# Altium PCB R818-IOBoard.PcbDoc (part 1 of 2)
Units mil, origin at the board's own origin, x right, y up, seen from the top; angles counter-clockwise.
Board outline 4330.71 x 4330.71 mil, 4 copper layers (Top Layer, Layer 2, Layer 1, Bottom Layer), stack 33.574 mil thick; 161 components, 167 nets, 792 pads, 698 vias.
Unrouted connection lines stored in the file: 71.
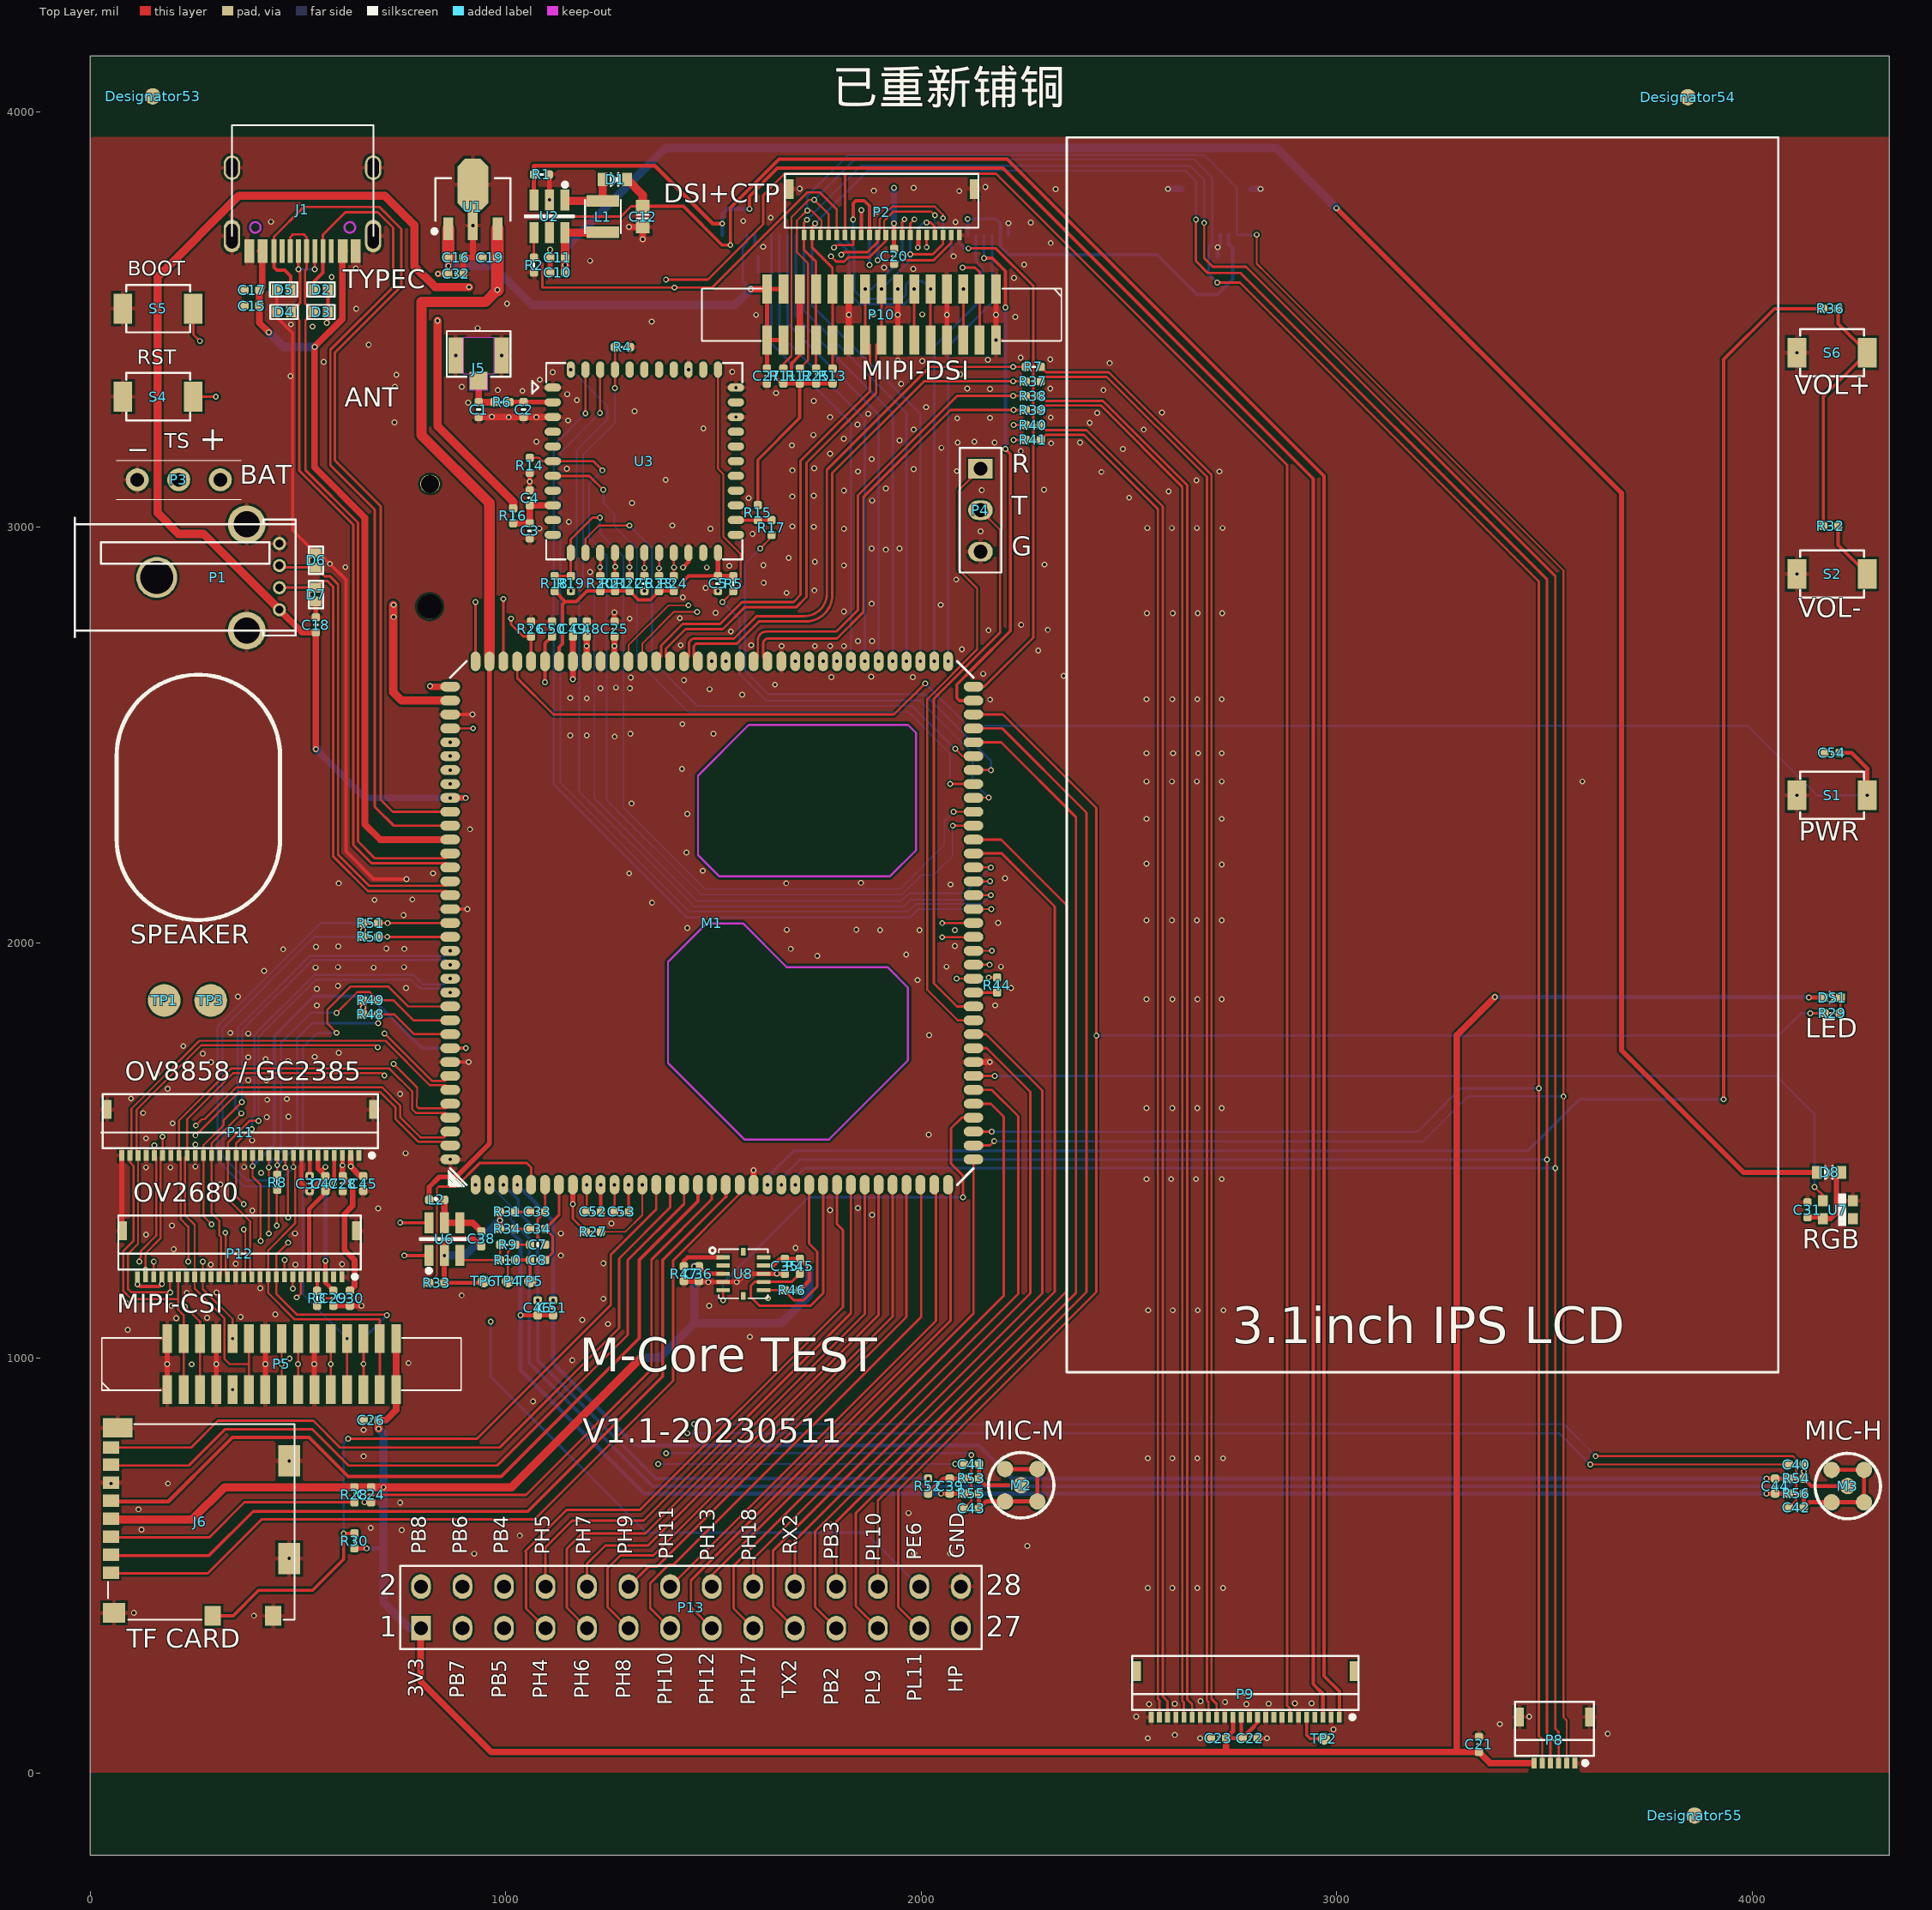
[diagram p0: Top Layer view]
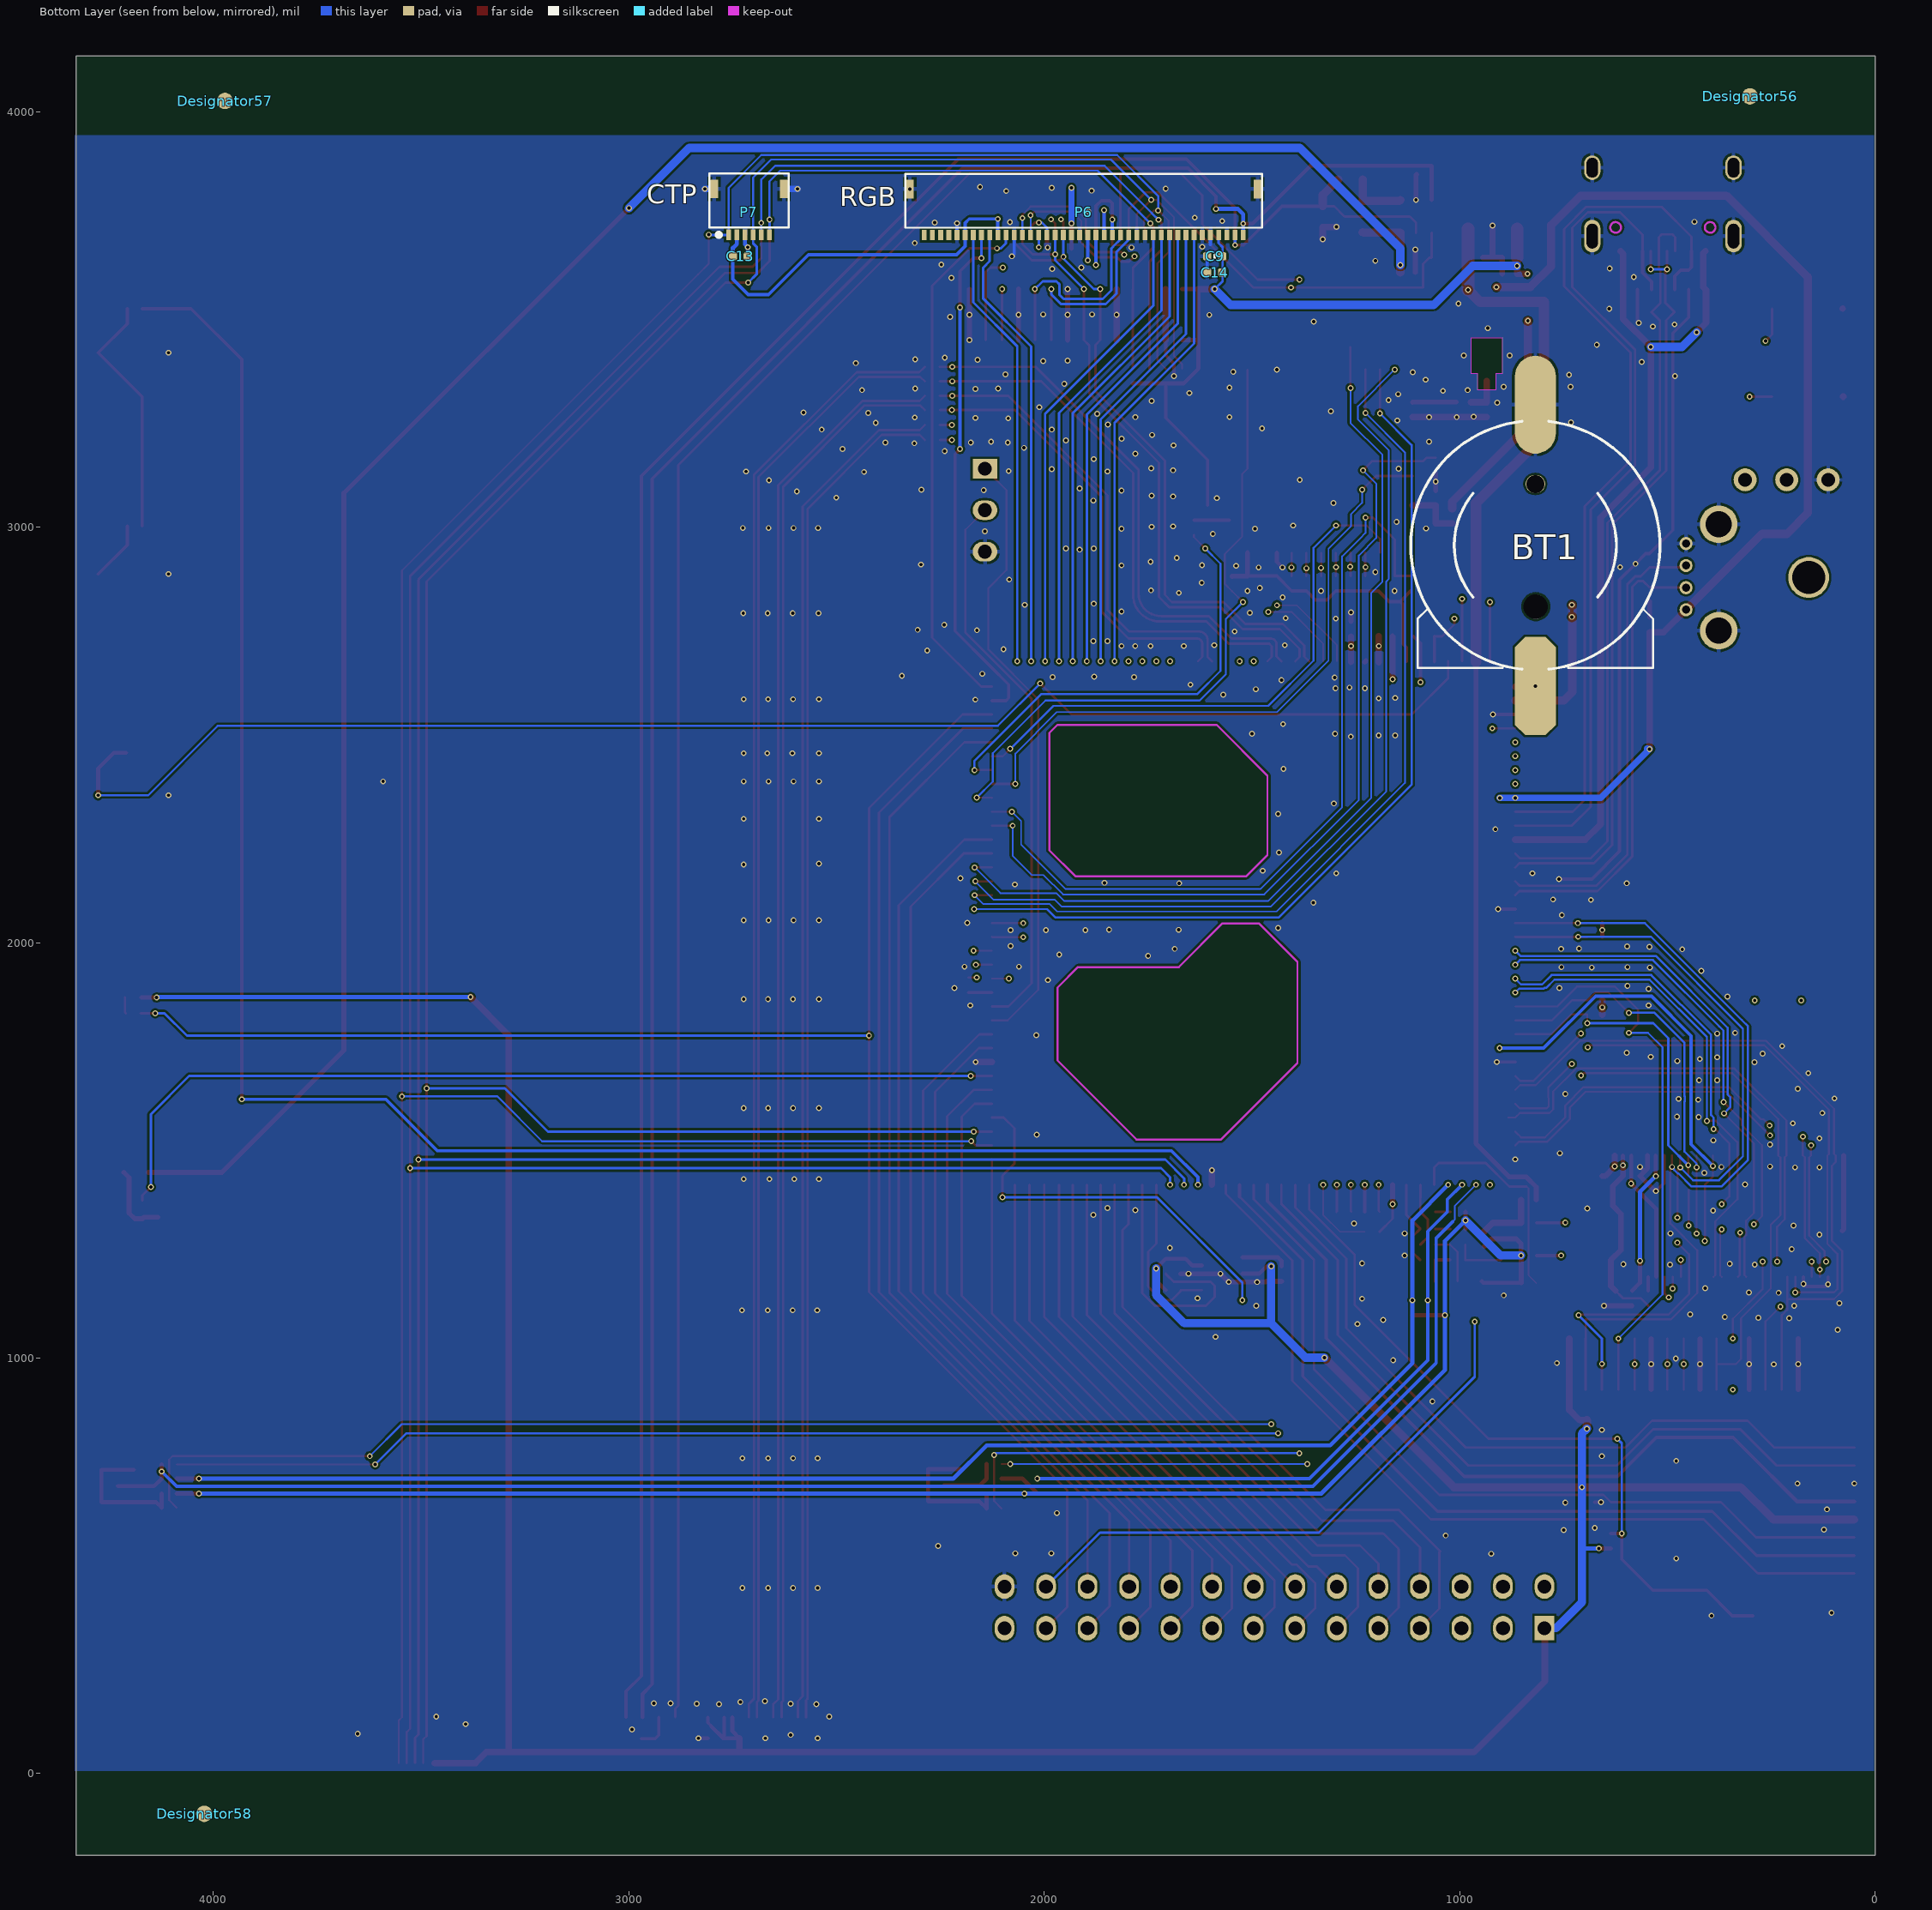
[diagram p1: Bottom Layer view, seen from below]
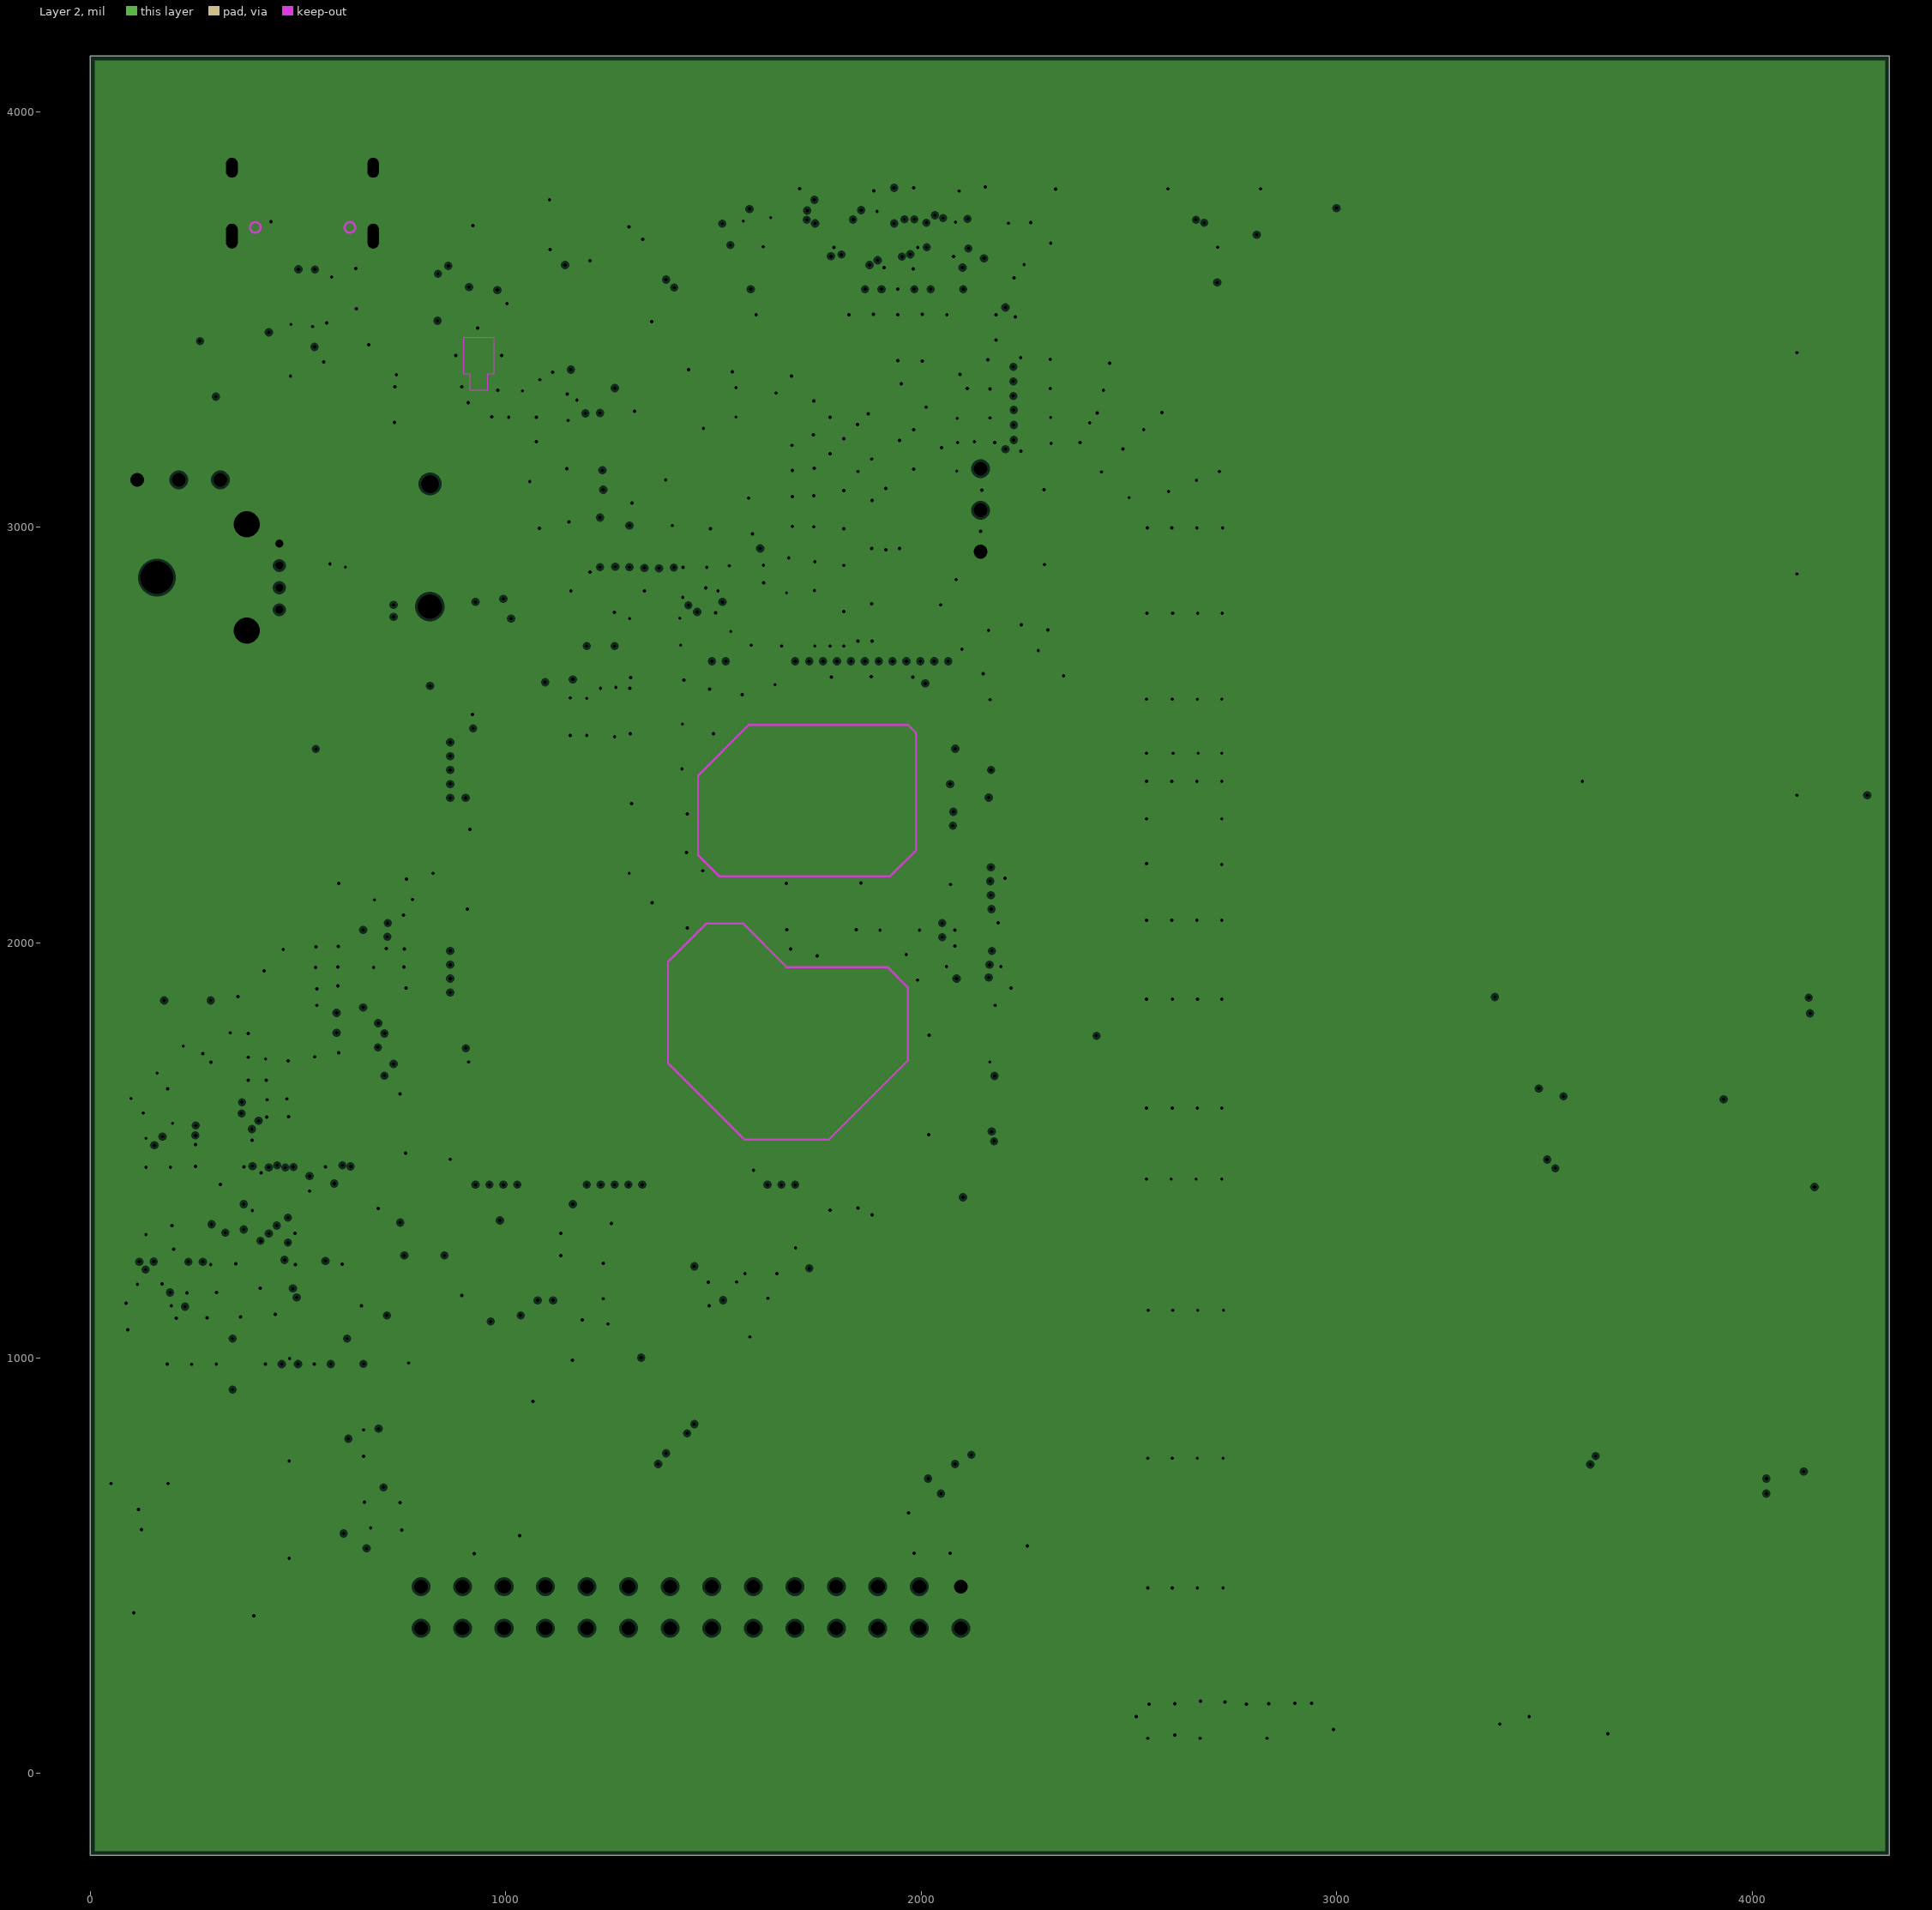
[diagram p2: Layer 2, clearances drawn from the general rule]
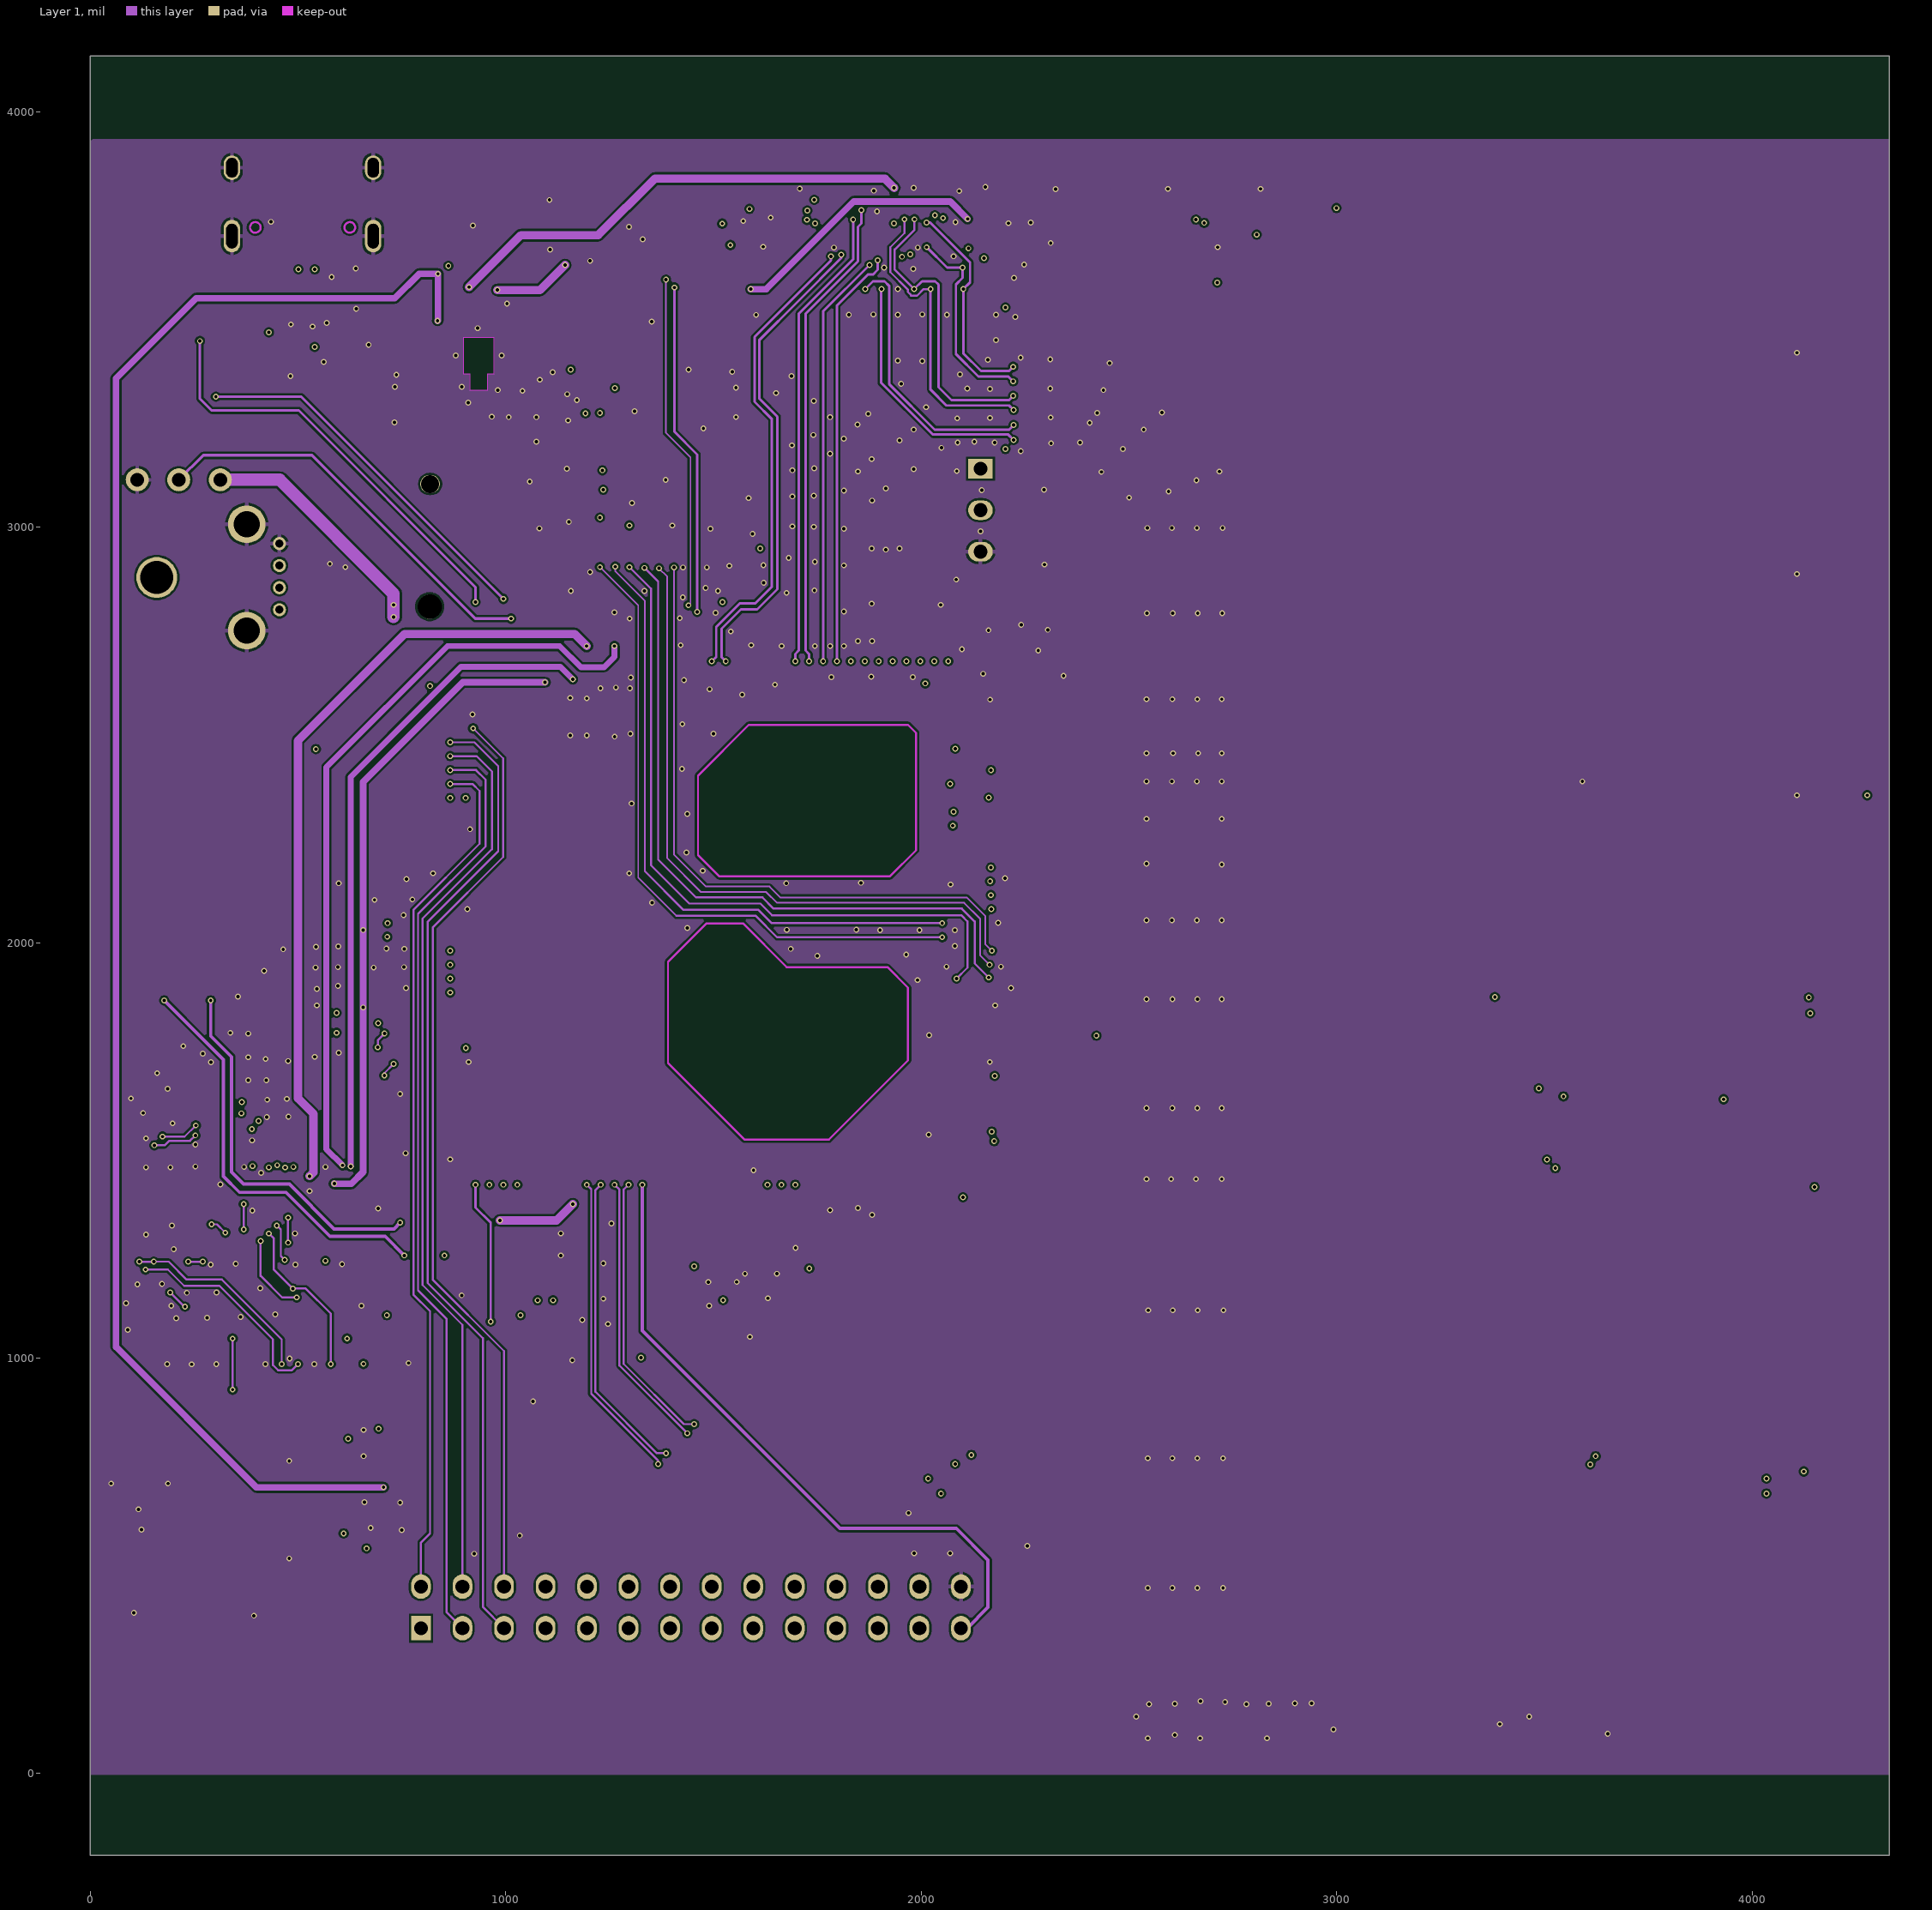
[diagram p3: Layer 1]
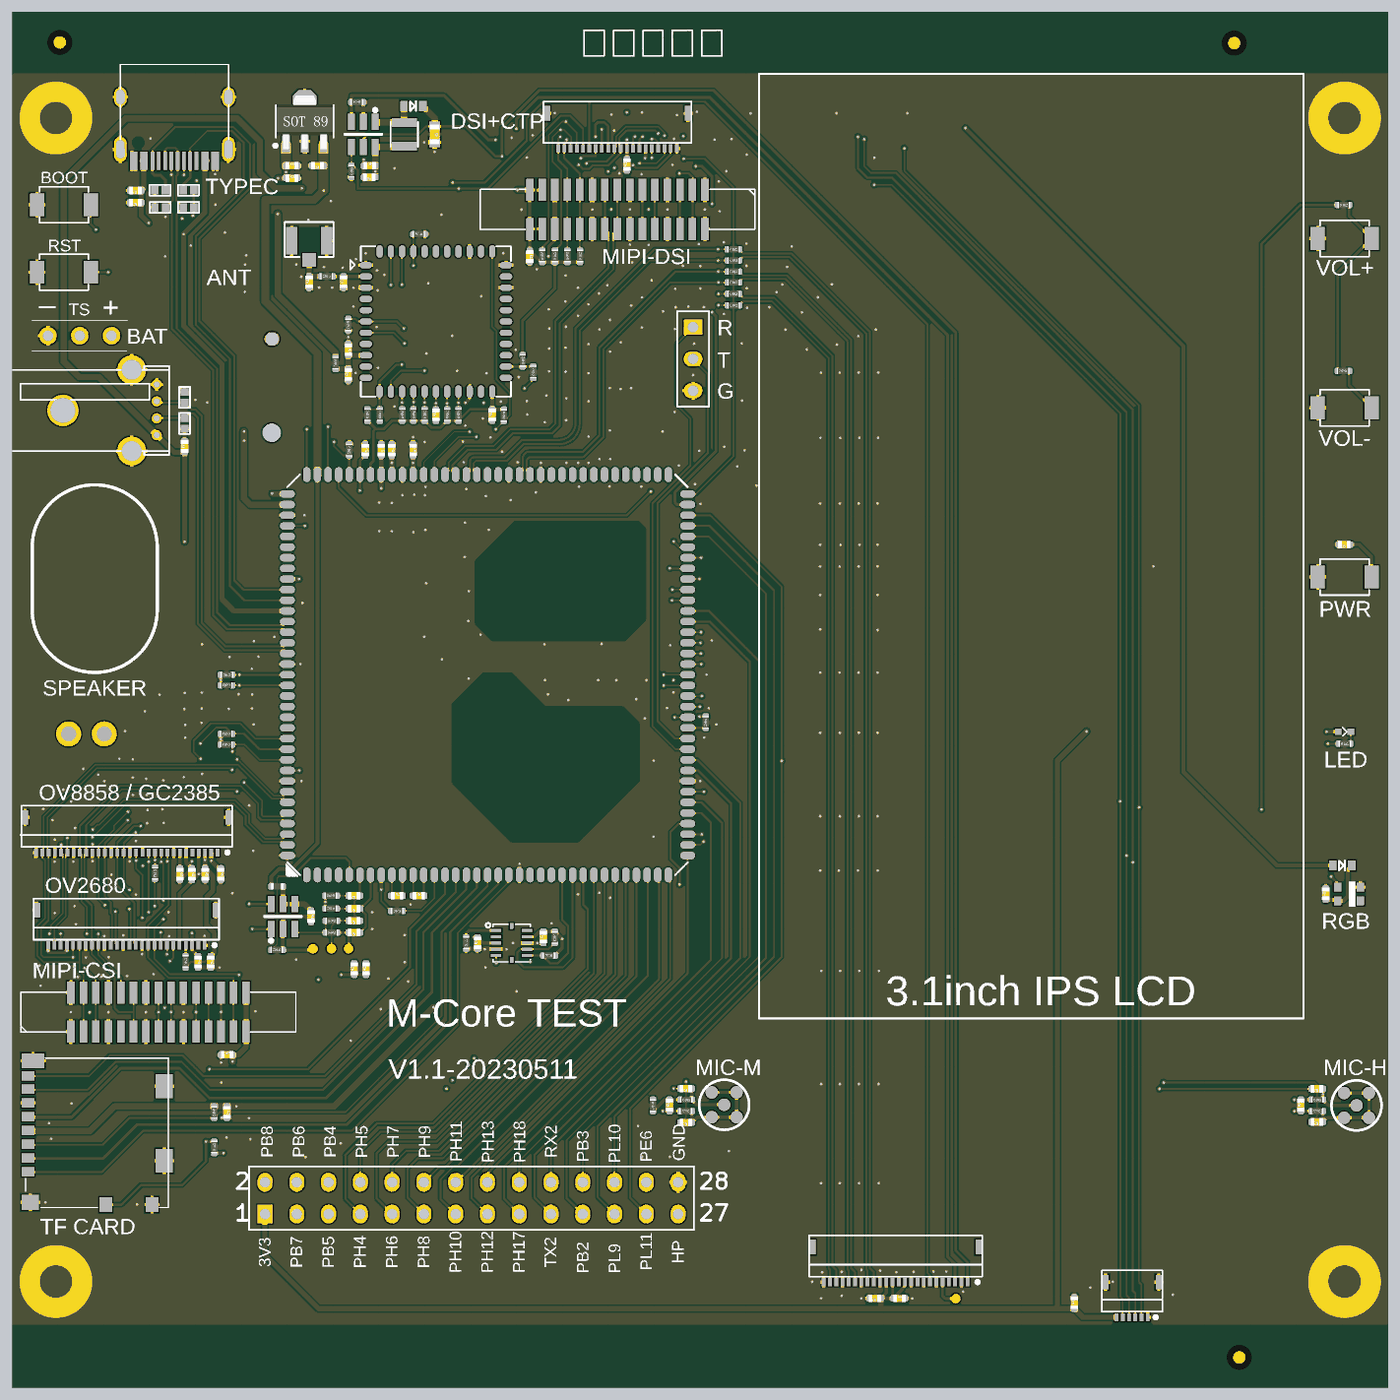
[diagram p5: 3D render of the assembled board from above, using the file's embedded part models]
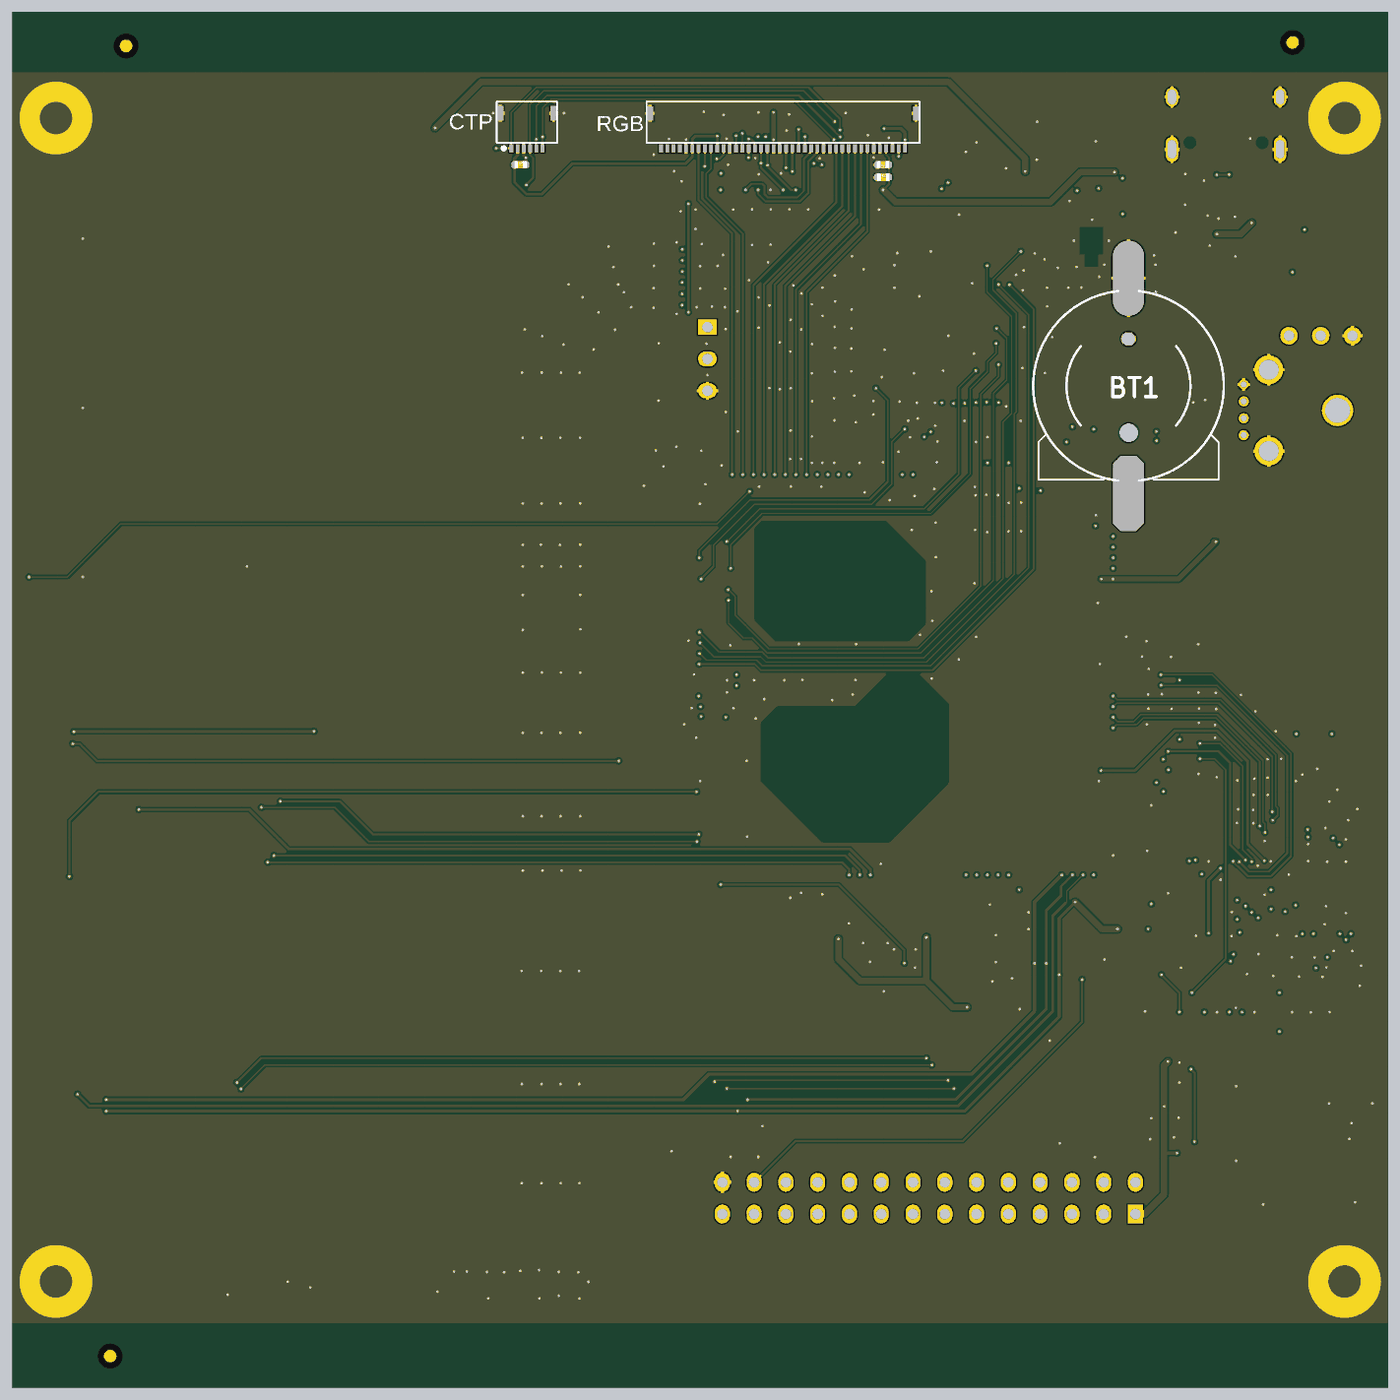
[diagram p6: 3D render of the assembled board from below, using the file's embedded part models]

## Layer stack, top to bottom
Top Solder: solder mask 0.4, Solder Resist, Dk 3.5
Top Layer: signal copper 1.378
Dielectric1: prepreg 18, PR-4, Dk 4.4
Layer 2: plane copper 0.709, net GND
Dielectric 2: prepreg 8.6, PP-023, Dk 4.5
Layer 1: signal copper 0.709
Dielectric 3: prepreg 2.8, PP-006, Dk 4.1
Bottom Layer: signal copper 1.378
Bottom Solder: solder mask 0.4, Solder Resist, Dk 3.5

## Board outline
0,0 0,3937.01 0,4133.86 4330.71,4133.86 4330.71,3937.01 4330.71,0 4330.71,-196.85 0,-196.85

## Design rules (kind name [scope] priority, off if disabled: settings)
AssemblyTestPointUsage [All] p1 off:
AssemblyTestpoint [All] p1 off: testpointundercomponent=TRUE minsize=40 maxsize=100 preferedsize=60 minholesize=0 maxholesize=40 preferedholesize=32 testpointgrid=1 usegrid=TRUE gridtolerance=0.01 allowsidetop=TRUE allowsidebottom=TRUE
Clearance Clearance_1 [All] p1: gap=5 ignorepadtopadclearanceinfootprint=FALSE
Clearance [InPolygon] p2: gap=6 ignorepadtopadclearanceinfootprint=FALSE
ComponentClearance [All] p1 off: gap=1 collisioncheckmode=3 verticalgap=1 showdistances=FALSE
DiffPairsRouting [All] p1: maxlimit=20 minlimit=5.5 mostfreqgap=7 toplayer_minwidth=4 toplayer_maxwidth=8 toplayer_prefwidth=4.6 midlayer1_minwidth=4 midlayer1_maxwidth=8 midlayer1_prefwidth=4.6 bottomlayer_minwidth=4 bottomlayer_maxwidth=8 bottomlayer_prefwidth=4.6 maxuncoupledlength=3000
FabricationTestPointUsage TestPointUsage [All] p1 off: valid=0 allowmultiple=FALSE
FabricationTestpoint Testpoint [(IsPad And (OnTopLayer Or OnBottomLayer))] p1 off: side=3 testpointundercomponent=TRUE minsize=40 maxsize=100 preferedsize=60 minholesize=0 maxholesize=40 preferedholesize=32 testpointgrid=1 allowsidetop=TRUE allowsidebottom=TRUE usegrid=TRUE gridtolerance=0.01
Height [All] p1 off: minheight=0 maxheight=1000 prefheight=500
HoleSize [All] p1: absolutevalues=TRUE maxlimit=150 minlimit=1 maxpercent=80.000 minpercent=20.000
HoleToHoleClearance [All] p1: gap=0 allowstackedmicrovias=TRUE
MinimumSolderMaskSliver [All] p1 off: minsoldermaskwidth=1
NetAntennae [All] p1: netantennaetolerance=10
PlaneClearance [All] p1: clearance=6
PlaneConnect [All] p1: planeconnectstyle=Direct reliefexpansion=20 reliefentries=4 reliefconductorwidth=25 reliefairgap=10
PolygonConnect PolygonConnect_1 [All vs IsPad] p1: connectstyle=Relief reliefconductorwidth=10 reliefentries=4 polygonreliefangle="90 Angle" airgapwidth=6
PolygonConnect PolygonConnect_isvia [All vs IsVia] p2: connectstyle=Direct reliefconductorwidth=10 reliefentries=4 polygonreliefangle="90 Angle" airgapwidth=10
PolygonConnect [All] p3: connectstyle=Direct reliefconductorwidth=8 reliefentries=4 polygonreliefangle="90 Angle" airgapwidth=10
RoutingVias [All] p1: holewidth=8 width=14 viastyle="Through Hole" minholewidth=8 minwidth=14 maxholewidth=100 maxwidth=100
ShortCircuit [InNet('WIFI') vs InNet('GND')] p1 off: allowed=FALSE
SilkToSilkClearance [All] p1: silktosilkclearance=0
SilkToSolderMaskClearance SilkscreenOverComponentPads [IsPad] p1: minsilkscreentomaskgap=0 clearancetoexposedcopper=TRUE
SolderMaskExpansion [All] p1: expansion=4 istentingtop=FALSE
Width [All] p1: maxlimit=100 minlimit=4 preferedwidth=4.72
14 further rules are at their usual default settings.

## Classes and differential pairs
differential pair D3: +D3_P -D3_N
differential pair D2: +D2_P -D2_N
differential pair D1: +D1_P -D1_N
differential pair D0: +D0_P -D0_N
differential pair CK: +CK_P -CK_N
differential pair USB1: +USB1_P -USB1_N
differential pair USB0: +USB0_P -USB0_N

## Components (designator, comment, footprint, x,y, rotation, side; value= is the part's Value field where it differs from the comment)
BT1 "BAT" BAT1220 817.7,2956.43 r180 bottom locked
C1 "NC" C0402 934.7,3283 r90 top
C2 "NC" C0402 1042.7,3283 r90 top
C3 "10uF" C0402 1057.69,2991.37 r90 top
C4 "0.1uF" C0402 1057.69,3070.37 r270 top
C5 "2.2uF" C0402 1510.69,2864.37 r90 top
C6 "NC" C0402 1333.57,2864.37 r90 top
C7 "10uF" C0402 1076.7,1273 r180 top
C8 "10uF" C0402 1076.7,1236 r180 top
C9 "0.1uF" C0402 1589.7,3652 r0 bottom
C10 "10uF" C0402 1124.7,3613 r180 top
C11 "10uF" C0402 1124.7,3649 r0 top
C12 "1uF 50V" C0603 1329.7,3747.7 r270 top
C13 "0.1uF" C0402 2731.7,3652 r180 bottom
C14 "10uF" C0402 1589.7,3613 r180 bottom
C15 "0.1uF" C0402 388.7,3533 r180 top
C16 "10uF" C0402 879.7,3649 r0 top
C17 "10uF" C0402 388.7,3571 r180 top
C18 "10uF" C0402 542.7,2765 r90 top
C19 "10uF" C0402 961.7,3649 r180 top
C20 "0.1uF" C0402 1934.7,3652 r90 top
C21 "0.1uF" C0402 3342.7,70 r90 top
C22 "0.1uF" C0402 2791.7,85 r0 top
C23 "10uF" C0402 2715.7,85 r180 top
C24 "0.1uF" C0402 675.7,671 r270 top
C25 "0.1uF" C0402 1261.7,2755 r270 top
C26 "10uF" C0402 675.7,851 r0 top
C27 "10uF" C0402 1628.7,3364 r270 top
C28 "10uF" C0402 607.58,1420 r270 top
C29 "10uF" C0402 584.7,1144 r270 top
C30 "10uF" C0402 624.7,1144 r270 top
C31 "0.1uF" C0402 4133.7,1357 r90 top
C32 "0.1uF" C0402 879.7,3610 r0 top
C33 "0.1uF" C0402 1076.7,1352 r180 top
C34 "0.1uF" C0402 1076.7,1311 r180 top
C35 "0.1uF" C0402 1671.7,1221 r90 top
C36 "0.1uF" C0402 1464.7,1203 r90 top
C37 "10uF" C0402 527.7,1420 r270 top
C38 "10uF" C0402 940.7,1287 r270 top
C39 "10uF" C0402 2068.7,692 r90 top
C40 "0.1uF" C0402 4106.7,744 r180 top
C41 "0.1uF" C0402 2120.7,745 r180 top
C42 "0.1uF" C0402 4106.7,640 r180 top
C43 "0.1uF" C0402 2120.7,638 r180 top
C44 "10uF" C0402 4055.7,692 r90 top
C45 "10uF" C0402 656.7,1420 r270 top
C46 "1uF" C0402 1076.7,1121 r90 top
C47 "10uF" C0402 565.7,1420 r270 top
C48 "0.1uF" C0402 1194.7,2755 r270 top
C49 "0.1uF" C0402 1161.7,2755 r270 top
C50 "0.1uF" C0402 1111.2,2755 r270 top
C51 "1uF" C0402 1113.7,1121 r90 top
C52 "100pF" C0402 1210.7,1352 r0 top
C53 "100pF" C0402 1278.7,1352 r0 top
C54 "0.1uF" C0402 4192.7,2457 r180 top
D1 "MSK4010" SOD523 1262.7,3837 r0 top
D2 "D-TVS" 0402TVS 554.97,3572 r180 top
D3 "D-TVS" 0402TVS 554.97,3518 r180 top
D4 "D-TVS" 0402TVS 465.97,3518 r0 top
D5 "D-TVS" 0402TVS 465.43,3572 r0 top
D6 "D-TVS" 0402TVS 542.7,2920 r270 top
D7 "D-TVS" 0402TVS 542.7,2838 r90 top
D8 "Diode" SOD523 4186,1447 r0 top
Designator53 "Comment" MARKER-C 150,4037 r0 top
Designator54 "Comment" MARKER-C 3845.72,4035.05 r0 top
Designator55 "Comment" MARKER-C 3861.72,-100.95 r0 top
Designator56 "Comment" MARKER-C 301.28,4037.05 r180 bottom
Designator57 "Comment" MARKER-C 3972.28,4026.05 r180 bottom
Designator58 "Comment" MARKER-C 4022.28,-96.95 r180 bottom
DS1 "LED" LED0402 4193.05,1867.84 r0 top
J1 "USB-TypeC-16P" USB-TYPEC-16P 510.7,3765 r180 top locked
J5 "ipex" "I-PEX SOCKET" 934.7,3413.02 r0 top
J6 "TF5033981892" TFCARD-1040310811 42.54,605.76 r270 top locked
L1 "10uH" VLS252010 1233.7,3747.7 r270 top
L2 "磁珠" L0402 833.7,1381 r0 top
M1 "MCORE-R818_V3" 818CORE 1496.06,2047.24 r0 top locked
M2 "MIC" MIC-T 2240.7,694 r225 top
M3 "MIC" MIC-T 4230.7,692 r315 top
P1 "USB A RA STACKED" "USB-A STAND" 307.34,2879 r90 top locked
P2 "FFC20" FFC/SM0.5-1H20 1904.98,3758.63 r180 top locked
P3 "Header 3" HDR1X3-xiao 212.7,3114 r180 top
P4 "Header 3" HDR1X3 2142.7,3141 r270 top locked
P5 "Header 15-CSI" MIPI_CSI_1.0_30PIN 460.44,985.58 r90 top locked
P6 "FFC40-RGBLCD" FFC/SM0.5-1H40 1904.98,3758.63 r0 bottom locked
P7 "FPC6" FFC/SM0.5-1H6-CTP 2710.7,3759 r0 bottom locked
P8 "FPC6-3.1" FFC/SM0.5-1H6-CTP-F 3524.6,80.63 r0 top
P9 "Header 24" FFC/SM0.5-1H24 2780.23,190.95 r180 top
P10 "Header 15-DSI" MIPI_CSI_1.0_30PIN 1904.48,3511.58 r270 top locked
P11 "FPC30" FFC/SM0.5-1H30 360.7,1543 r180 top locked
P12 "Header 26" FFC/SM0.5-1H26 359.21,1251 r180 top locked
P13 "Header 14X2" HDR2X14 795.7,350 r0 top locked
R1 "2R7" R0402 1085.7,3849 r180 top
R2 "150K" R0402 1067.7,3631 r90 top
R3 "0R" R0402 545.7,1144 r90 top
R4 "NC/100K" R0402 1280.69,3433.37 r180 top
R5 "100K" R0402 1547.7,2864 r270 top
R6 "0R" R0402 990.7,3301 r180 top
R7 "0R" R0402 2269.7,3386 r0 top
R8 "0R" R0402 449.7,1423 r270 top
R9 "150K 1%" R0402 1004.7,1273 r0 top
R10 "150K 1%" R0402 1004.7,1236 r0 top
R11 "10K" R0402 1668.2,3364 r90 top
R12 "10K" R0402 1707.7,3364 r90 top
R13 "2K" R0402 1786.7,3364 r90 top
R14 "NC/100K" R0402 1057.69,3149 r270 top
R15 "47K" R0402 1606.7,3035.17 r90 top
R16 "0R" R0402 1017.7,3027.37 r90 top
R17 "NC" R0402 1639.7,2999 r90 top
R18 "100K" R0402 1117.7,2864.37 r90 top
R19 "NC/100K" R0402 1156.69,2864.37 r90 top
R20 "47K" R0402 1227.44,2864.37 r90 top
R21 "47K" R0402 1262.82,2864.37 r90 top
R22 "47K" R0402 1298.19,2864.37 r90 top
R23 "47K" R0402 1368.94,2864.37 r90 top
R24 "47K" R0402 1404.32,2864.37 r90 top
R25 "2K" R0402 1747.2,3364 r90 top
R26 "10K" R0402 1060.7,2755 r270 top
R27 "47K" R0402 1210.7,1304 r0 top
R28 "10K" R0402 635.7,671 r270 top
R29 "2K" R0402 4193.05,1830 r0 top
R30 "10K" R0402 635.7,560 r90 top
R31 "22R" R0402 1003.7,1352 r180 top
R32 "820R" R0402 4189.7,3003 r180 top
R33 "0R" R0402 833.7,1181 r180 top
R34 "22R" R0402 1003.7,1311 r180 top
R36 "680R" R0402 4189.7,3526 r0 top
R37 "0R" R0402 2269.7,3351 r0 top
R38 "0R" R0402 2269.7,3316 r0 top
R39 "0R" R0402 2269.7,3282 r0 top
R40 "0R" R0402 2269.7,3246 r0 top
R41 "0R" R0402 2269.7,3210 r0 top
R44 "22R" R0402 2182.7,1898 r270 top
R45 "2K" R0402 1707.7,1221 r270 top
R46 "2K" R0402 1689.7,1163.63 r180 top
R47 "0R" R0402 1428.7,1203 r90 top
R48 "100K" R0402 674.7,1827 r180 top
R49 "100K" R0402 674.7,1861 r180 top
R50 "2K" R0402 674.7,2014 r180 top
R51 "2K" R0402 674.7,2047 r0 top
R52 "1K" R0402 2016.7,692 r270 top
R53 "1K" R0402 2120.7,710 r0 top
R54 "2K" R0402 4106.7,710 r0 top
R55 "0R" R0402 2120.7,674 r180 top
R56 "0R" R0402 4106.7,674 r180 top
S1 "SW-BUTTON" MINIBUTTON 4193.28,2354.8 r180 top
S2 "SW-BUTTON" MINIBUTTON 4192.82,2887.28 r0 top
S4 "SW-BUTTON" MINIBUTTON 162.7,3314 r0 top
S5 "SW-BUTTON" MINIBUTTON 162.7,3526 r0 top
S6 "SW-BUTTON" MINIBUTTON 4192.82,3419.92 r0 top
TP1 "TEST POINT" TEST-POINT2 177.7,1861 r225 top
TP2 "TEST POINT" TEST-POINT 2969.7,84 r270 top
TP3 "TEST POINT" TEST-POINT2 289.7,1861 r180 top
TP4 "TEST POINT" TEST-POINT 1004.7,1185 r0 top
TP5 "TEST POINT" TEST-POINT 1058.7,1185 r0 top
TP6 "TEST POINT" TEST-POINT 946.7,1185 r270 top
U1 "MD7671E" SOT89N 920.7,3789 r90 top
U2 "MT9284-28J" SOT23-6 1105.11,3748.26 r270 top
U3 "RTL8723DS" RTL8723DS 1333.56,3158.9 r0 top locked
U6 "PAM8301" SOT23-6 852.1,1286.37 r90 top
U7 "LED" WS2812LED-2020 4207.05,1357 r180 top
U8 "MMA7660" SOP10-PT05-MMA7660FC-H1A 1571.88,1203 r270 top locked

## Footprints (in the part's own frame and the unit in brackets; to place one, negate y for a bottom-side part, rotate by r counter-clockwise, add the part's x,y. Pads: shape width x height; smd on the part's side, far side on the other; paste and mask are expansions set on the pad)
0402TVS [mm]
  rect 0.6x0.65 smd mask+0.051: 1(-0.425,0) 2(0.425,0)
  silkscreen extent -0.84,-0.43 0.84,0.43
818CORE [mm]
  oval 0.6x1.2 smd mask+0.051: 1(-14.45,-16) 2(-13.6,-16) 3(-12.75,-16) 4(-11.9,-16) 5(-11.05,-16) 6(-10.2,-16) 7(-9.35,-16) 8(-8.5,-16) 9(-7.65,-16) 10(-6.8,-16) 11(-5.95,-16) 12(-5.1,-16) 13(-4.25,-16) 14(-3.4,-16) 15(-2.55,-16) 16(-1.7,-16) 17(-0.85,-16) 18(0,-16) 19(0.85,-16) 20(1.7,-16) 21(2.55,-16) 22(3.4,-16) 23(4.25,-16) 24(5.1,-16) 25(5.95,-16) 26(6.8,-16) 27(7.65,-16) 28(8.5,-16) 29(9.35,-16) 30(10.2,-16) 31(11.05,-16) 32(11.9,-16) 33(12.75,-16) 34(13.6,-16) 35(14.45,-16) 71(14.45,16) 72(13.6,16) 73(12.75,16) 74(11.9,16) 75(11.05,16) 76(10.2,16) 77(9.35,16) 78(8.5,16) 79(7.65,16) 80(6.8,16) 81(5.95,16) 82(5.1,16) 83(4.25,16) 84(3.4,16) 85(2.55,16) 86(1.7,16) 87(0.85,16) 88(0,16) 89(-0.85,16) 90(-1.7,16) 91(-2.55,16) 92(-3.4,16) 93(-4.25,16) 94(-5.1,16) 95(-5.95,16) 96(-6.8,16) 97(-7.65,16) 98(-8.5,16) 99(-9.35,16) 100(-10.2,16) 101(-11.05,16) 102(-11.9,16) 103(-12.75,16) 104(-13.6,16) 105(-14.45,16)
  oval 1.2x0.6 smd mask+0.051: 36(16,-14.45) 37(16,-13.6) 38(16,-12.75) 39(16,-11.9) 40(16,-11.05) 41(16,-10.2) 42(16,-9.35) 43(16,-8.5) 44(16,-7.65) 45(16,-6.8) 46(16,-5.95) 47(16,-5.1) 48(16,-4.25) 49(16,-3.4) 50(16,-2.55) 51(16,-1.7) 52(16,-0.85) 53(16,0) 54(16,0.85) 55(16,1.7) 56(16,2.55) 57(16,3.4) 58(16,4.25) 59(16,5.1) 60(16,5.95) 61(16,6.8) 62(16,7.65) 63(16,8.5) 64(16,9.35) 65(16,10.2) 66(16,11.05) 67(16,11.9) 68(16,12.75) 69(16,13.6) 70(16,14.45) 106(-16,14.45) 107(-16,13.6) 108(-16,12.75) 109(-16,11.9) 110(-16,11.05) 111(-16,10.2) 112(-16,9.35) 113(-16,8.5) 114(-16,7.65) 115(-16,6.8) 116(-16,5.95) 117(-16,5.1) 118(-16,4.25) 119(-16,3.4) 120(-16,2.55) 121(-16,1.7) 122(-16,0.85) 123(-16,0) 124(-16,-0.85) 125(-16,-1.7) 126(-16,-2.55) 127(-16,-3.4) 128(-16,-4.25) 129(-16,-5.1) 130(-16,-5.95) 131(-16,-6.8) 132(-16,-7.65) 133(-16,-8.5) 134(-16,-9.35) 135(-16,-10.2) 136(-16,-11.05) 137(-16,-11.9) 138(-16,-12.75) 139(-16,-13.6) 140(-16,-14.45)
  Keep-Out Layer lines w0.127: -2.682,-8.566 -2.682,-2.376 -0.328,-0.023 1.899,-0.023 4.569,-2.692 10.735,-2.692 11.991,-3.948 11.991,-8.405 7.162,-13.233 1.986,-13.233 -2.682,-8.566 ; -0.848,4.155 -0.848,9.008 2.264,12.12 11.989,12.12 12.487,11.622 12.487,4.451 10.881,2.845 0.462,2.845 -0.848,4.155
  silkscreen extent -16.12,-16.12 16,16
BAT1220 [mm]
  oval 1.2x1.1 hole 1.1 unplated: 0(0,3.748)
  oval 1.2x1.5 hole 1.5 unplated: 0(0.025,-3.752)
  oct 2.5x6 smd: 1(0,-8.602)
  oval 2.5x6 smd: 2(0,8.598)
  silkscreen extent -7.62,-7.58 7.62,7.57
C0402 [mil]
  rrect50% 20x20 smd mask+2: 1(-18,0) 2(18,0)
  silkscreen extent 0,-4 0,4, body extent -19,-12 20,12, height 8
C0603 [mil]
  rect 31.5x33.46 smd: 1(-25,0) 2(25,0)
  silkscreen extent -5,-14 5,14, body extent -31,-16 32,16, height 12
FFC/SM0.5-1H6-CTP [mm] "Connector; FH12 Series; 6 Position; 0.5mm Spaced Bottom Contact"
  rect 0.3x0.65 smd: 1(1.25,1.405) 2(0.75,1.405) 3(0.25,1.405) 4(-0.25,1.405) 5(-0.75,1.405) 6(-1.25,1.405)
  rect 0.5x1.15 smd: G(-2.135,-1.405) G(2.135,-1.405)
  silkscreen extent -2.42,-2.34 2.42,1.53
FFC/SM0.5-1H6-CTP-F [mm] "Connector; FH12 Series; 6 Position; 0.5mm Spaced Bottom Contact"
  rect 0.3x0.65 smd: 1(1.25,-1.405) 2(0.75,-1.405) 3(0.25,-1.405) 4(-0.25,-1.405) 5(-0.75,-1.405) 6(-1.25,-1.405)
  rect 0.5x1.15 smd: G(-2.135,1.405) G(2.135,1.405)
  silkscreen extent -2.42,-1.53 2.42,2.34
FFC/SM0.5-1H20 [mm] "Connector; FH12 Series; 20 Position; 0.5mm Spaced Bottom Contact"
  rect 0.3x0.65 smd: 1(-4.75,1.405) 2(-4.25,1.405) 3(-3.75,1.405) 4(-3.25,1.405) 5(-2.75,1.405) 6(-2.25,1.405) 7(-1.75,1.405) 8(-1.25,1.405) 9(-0.75,1.405) 10(-0.25,1.405) 11(0.25,1.405) 12(0.75,1.405) 13(1.25,1.405) 14(1.75,1.405) 15(2.25,1.405) 16(2.75,1.405) 17(3.25,1.405) 18(3.75,1.405) 19(4.25,1.405) 20(4.75,1.405)
  rect 0.5x1.2 smd: G(-5.635,-1.405) G(5.635,-1.405)
  silkscreen extent -5.91,-2.34 5.92,0.96
FFC/SM0.5-1H24 [mm] "Connector; FH12 Series; 24 Position; 0.5mm Spaced Bottom Contact"
  rect 0.3x0.65 smd: 1(-5.75,1.405) 2(-5.25,1.405) 3(-4.75,1.405) 4(-4.25,1.405) 5(-3.75,1.405) 6(-3.25,1.405) 7(-2.75,1.405) 8(-2.25,1.405) 9(-1.75,1.405) 10(-1.25,1.405) 11(-0.75,1.405) 12(-0.25,1.405) 13(0.25,1.405) 14(0.75,1.405) 15(1.25,1.405) 16(1.75,1.405) 17(2.25,1.405) 18(2.75,1.405) 19(3.25,1.405) 20(3.75,1.405) 21(4.25,1.405) 22(4.75,1.405) 23(5.25,1.405) 24(5.75,1.405)
  rect 0.5x1.2 smd: G(-6.635,-1.405) G(6.635,-1.405)
  silkscreen extent -6.92,-2.34 6.92,1.53
FFC/SM0.5-1H26 [mm] "Connector; FH12 Series; 30 Position; 0.5mm Spaced Bottom Contact"
  rect 0.3x0.65 smd: 1(-6.25,1.405) 2(-5.75,1.405) 3(-5.25,1.405) 4(-4.75,1.405) 5(-4.25,1.405) 6(-3.75,1.405) 7(-3.25,1.405) 8(-2.75,1.405) 9(-2.25,1.405) 10(-1.75,1.405) 11(-1.25,1.405) 12(-0.75,1.405) 13(-0.25,1.405) 14(0.25,1.405) 15(0.75,1.405) 16(1.25,1.405) 17(1.75,1.405) 18(2.25,1.405) 19(2.75,1.405) 20(3.25,1.405) 21(3.75,1.405) 22(4.25,1.405) 23(4.75,1.405) 24(5.25,1.405) 25(5.75,1.405) 26(6.25,1.405)
  rect 0.5x1.15 smd: G(-7.135,-1.405) G(7.135,-1.405)
  silkscreen extent -7.41,-2.34 7.42,1.53
FFC/SM0.5-1H30 [mm] "Connector; FH12 Series; 30 Position; 0.5mm Spaced Bottom Contact"
  rect 0.3x0.65 smd: 1(-7.25,1.405) 2(-6.75,1.405) 3(-6.25,1.405) 4(-5.75,1.405) 5(-5.25,1.405) 6(-4.75,1.405) 7(-4.25,1.405) 8(-3.75,1.405) 9(-3.25,1.405) 10(-2.75,1.405) 11(-2.25,1.405) 12(-1.75,1.405) 13(-1.25,1.405) 14(-0.75,1.405) 15(-0.25,1.405) 16(0.25,1.405) 17(0.75,1.405) 18(1.25,1.405) 19(1.75,1.405) 20(2.25,1.405) 21(2.75,1.405) 22(3.25,1.405) 23(3.75,1.405) 24(4.25,1.405) 25(4.75,1.405) 26(5.25,1.405) 27(5.75,1.405) 28(6.25,1.405) 29(6.75,1.405) 30(7.25,1.405)
  rect 0.5x1.15 smd: G(-8.135,-1.405) G(8.135,-1.405)
  silkscreen extent -8.41,-2.34 8.5,1.53
FFC/SM0.5-1H40 [mm] "Connector; FH12 Series; 40 Position; 0.5mm Spaced Bottom Contact"
  rect 0.3x0.65 smd: 1(-9.75,1.405) 2(-9.25,1.405) 3(-8.75,1.405) 4(-8.25,1.405) 5(-7.75,1.405) 6(-7.25,1.405) 7(-6.75,1.405) 8(-6.25,1.405) 9(-5.75,1.405) 10(-5.25,1.405) 11(-4.75,1.405) 12(-4.25,1.405) 13(-3.75,1.405) 14(-3.25,1.405) 15(-2.75,1.405) 16(-2.25,1.405) 17(-1.75,1.405) 18(-1.25,1.405) 19(-0.75,1.405) 20(-0.25,1.405) 21(0.25,1.405) 22(0.75,1.405) 23(1.25,1.405) 24(1.75,1.405) 25(2.25,1.405) 26(2.75,1.405) 27(3.25,1.405) 28(3.75,1.405) 29(4.25,1.405) 30(4.75,1.405) 31(5.25,1.405) 32(5.75,1.405) 33(6.25,1.405) 34(6.75,1.405) 35(7.25,1.405) 36(7.75,1.405) 37(8.25,1.405) 38(8.75,1.405) 39(9.25,1.405) 40(9.75,1.405)
  rect 0.5x1.15 smd: G(-10.635,-1.405) G(10.635,-1.405)
  silkscreen extent -10.91,-2.34 10.92,0.96
HDR1X3 [mm]
  rect 1.2x1.5 hole 0.85: 1(0,0)
  oval 1.2x1.5 hole 0.85: 2(2.54,0) 3(5.08,0)
  silkscreen extent -1.27,-1.27 6.35,1.27
HDR1X3-xiao [mm]
  round 1.4 hole 0.85: 1(-2.54,0) 2(0,0) 3(2.54,0)
  silkscreen extent -3.81,-1.2 3.81,1.2
HDR2X14 [mm]
  rect 1.2x1.5 hole 0.85: 1(0,0)
  oval 1.2x1.5 hole 0.85: 2(0,2.54) 3(2.54,0) 4(2.54,2.54) 5(5.08,0) 6(5.08,2.54) 7(7.62,0) 8(7.62,2.54) 9(10.16,0) 10(10.16,2.54) 11(12.7,0) 12(12.7,2.54) 13(15.24,0) 14(15.24,2.54) 15(17.78,0) 16(17.78,2.54) 17(20.32,0) 18(20.32,2.54) 19(22.86,0) 20(22.86,2.54) 21(25.4,0) 22(25.4,2.54) 23(27.94,0) 24(27.94,2.54) 25(30.48,0) 26(30.48,2.54) 27(33.02,0) 28(33.02,2.54)
  silkscreen extent -1.27,-1.27 34.29,3.81
"I-PEX SOCKET" [mm]
  rect 1.1x1.1 smd: 1(0,-1.55)
  rect 0.9x2.2 smd: 2(1.4,0) 3(-1.4,0)
  Keep-Out Layer pour cut-out: -0.95,1.1 -0.95,-1.101 -0.551,-1.101 -0.551,-2.101 0.001,-2.101 0.55,-2.101 0.55,-1.101 0.95,-1.101 0.95,1.1
  silkscreen extent -1.95,-1.3 1.95,1.5
L0402 [mil]
  rrect50% 20x20 smd mask+2: 1(-18,0) 2(18,0)
  silkscreen extent -3,-3 3,3, body extent -20,-10 21,10, height 14
LED0402 [mm]
  rect 0.55x0.5 smd: A(-0.508,0) K(0.508,0)
  silkscreen extent -0.15,-0.32 0.18,0.33
MARKER-C [mm]
  round 1 smd paste-1.016 mask+0.5: 0(0,0)
  Top Layer pour cut-out: -1.109,0 -1.072,-0.287 -0.961,-0.555 -0.785,-0.785 -0.555,-0.961 -0.287,-1.072 0,-1.109 0,-1.109 0.287,-1.072 0.555,-0.961 0.785,-0.785 0.961,-0.555 1.072,-0.287 1.109,0 1.109,0 1.072,0.287 0.961,0.555 0.785,0.785 0.555,0.961 0.287,1.072 0,1.109 0,1.109 -0.287,1.072 -0.555,0.961 -0.785,0.785 -0.961,0.555 -1.072,0.287 -1.109,0
MIC-T [mm]
  round 1 smd: 1(0,0) 2(-1.4,0) 2(0,-1.4) 2(0,1.4) 2(1.4,0)
  silkscreen extent -2,-2 2,2
MINIBUTTON [mil] "MINIBUTTON"
  rect 44.88x72.05 smd: 1(-84.42,0.08) 2(84.88,0.08)
  silkscreen extent -77,-57 77,57
MIPI_CSI_1.0_30PIN [mm]
  rect 1.77x0.6 smd: 1(-1.56,7) 1(1.56,7) 2(-1.56,6) 2(1.56,6) 3(-1.56,5) 3(1.56,5) 4(-1.56,4) 4(1.56,4) 5(-1.56,3) 5(1.56,3) 6(-1.56,2) 6(1.56,2) 7(-1.56,1) 7(1.56,1) 8(-1.56,0) 8(1.56,0) 9(-1.56,-1) 9(1.56,-1) 10(-1.56,-2) 10(1.56,-2) 11(-1.56,-3) 11(1.56,-3) 12(-1.56,-4) 12(1.56,-4) 13(-1.56,-5) 13(1.56,-5) 14(-1.56,-6) 14(1.56,-6) 15(-1.56,-7) 15(1.56,-7)
  silkscreen extent -1.6,-10.97 1.6,11
R0402 [mil]
  rrect50% 20x20 smd mask+2: 1(-18,0) 2(18,0)
  silkscreen extent -4,0 4,0, body extent -19,-10 21,10, height 14
RTL8723DS [mm]
  oval 1x0.5 smd: 1(-5.6,4.5) 2(-5.6,3.6) 3(-5.6,2.7) 4(-5.6,1.8) 5(-5.6,0.9) 6(-5.6,0) 7(-5.6,-0.9) 8(-5.6,-1.8) 9(-5.6,-2.7) 10(-5.6,-3.6) 11(-5.6,-4.5) 23(5.6,-4.5) 24(5.6,-3.6) 25(5.6,-2.7) 26(5.6,-1.8) 27(5.6,-0.9) 28(5.6,0) 29(5.6,0.9) 30(5.6,1.8) 31(5.6,2.7) 32(5.6,3.6) 33(5.6,4.5)
  oval 0.5x1 smd: 12(-4.5,-5.6) 13(-3.6,-5.6) 14(-2.7,-5.6) 15(-1.8,-5.6) 16(-0.9,-5.6) 17(0,-5.6) 18(0.9,-5.6) 19(1.8,-5.6) 20(2.7,-5.6) 21(3.6,-5.6) 22(4.5,-5.6) 34(4.5,5.6) 35(3.6,5.6) 36(2.7,5.6) 37(1.8,5.6) 38(0.9,5.6) 39(0,5.6) 40(-0.9,5.6) 41(-1.8,5.6) 42(-2.7,5.6) 43(-3.6,5.6) 44(-4.5,5.6)
  silkscreen extent -6.86,-6 6,6, body extent -6,-6 6,6, height 1.6
SOD523 [mm]
  rect 0.6x0.8 smd: A(-0.75,0) K(0.75,0)
  silkscreen extent -0.25,-0.38 0.2,0.38
SOP10-PT05-MMA7660FC-H1A [mm] "SOP10-PT05-MMA7660FC-H1A"
  rect 0.25x0.825 smd: 1(-1,-1.24) 2(-0.5,-1.24) 3(0,-1.24) 4(0.5,-1.24) 5(1,-1.24) 6(1,1.24) 7(0.5,1.24) 8(0,1.24) 9(-0.5,1.24) 10(-1,1.24)
  rect 0.475x0.3 smd: 11(-1.35,0) 12(1.35,0)
  silkscreen extent -1.6,-2.07 1.5,1.5, body extent -1.5,-1.75 1.5,1.75, height 0.9
SOT23-6 [mm] "SOT23, 5-Leads, Body 3.0x2.6mm (max), Pitch 0.95mm, IPC Medium Density"
  rect 1.3x0.55 smd: 1(-1,0.95) 2(-1,0) 3(-1,-0.95) 4(1,-0.95) 5(1,0) 6(1,0.95)
  silkscreen extent -2.06,-1.5 0.05,1.5, body extent -0.7,-1.5 0.7,1.5, height 1.1
SOT89N [mm] "SOT89, 3-Leads, Body 4.5x2.4 mm, Pitch 1.5mm, Lead Span 4.1mm, IPC Medium Density"
  rect 1.4x0.6 smd: 1(-1.8,1.5) 3(-1.8,-1.5)
  rect 1.8x0.6 smd: 2(-1.6,0)
  oct 3.2x1.9 smd: 2(0.9,0)
  silkscreen extent -2.07,-2.3 1.3,2.47, body extent -2.23,-2.25 2.07,2.25, height 1.51
TEST-POINT [mil]
  round 30 smd paste-15.75: 1(0,0)
TEST-POINT2 [mm]
  round 2 smd paste-0.4: 1(0,0)
TFCARD-1040310811 [mm] "TFCARD"
  rect 0.75x1 smd: 1(3.105,0.189) 2(2.005,0.189) 3(0.905,0.189) 4(-0.195,0.189) 5(-1.295,0.189) 6(-2.395,0.189) 7(-3.495,0.189) 8(-4.545,0.189)
  rect 1.2x1.35 smd: G1(5.565,0.365)
  rect 1.17x1.8 smd: G2(-5.755,0.59)
  rect 1.9x1.35 smd: G3(-3.73,11.075) G4(2.24,11.075)
  rect 1.2x1 smd: G5(5.74,10.1) G6(5.74,6.4)
  silkscreen extent -5.98,0 5.97,11.4
"USB-A STAND" [mm]
  round 0.8 hole 0.5: 1(-1.975,-3.75) 2(-0.625,-3.75) 3(0.725,-3.75) 4(2.075,-3.75)
  round 2.3 hole 1.6: 5(-3.25,-1.75) 6(3.25,-1.75)
  round 2.5 hole 2: 7(0,3.75)
  silkscreen extent -3.65,-4.75 3.65,8.75
USB-TYPEC-16P [mm]
  oval 1x1.5 hole 0.7 slot 1.2 at 90 deg: 0(-4.32,-2.548) 0(4.32,-2.548)
  oval 1x2 hole 0.7 slot 1.5 at 90 deg: 0(-4.32,1.632) 0(4.32,1.632)
  rect 0.3x1.45 smd: A1(-3.4,2.548) A4(-2.6,2.548) A5(-1.25,2.548) A6(-0.25,2.548) A7(0.25,2.548) A8(1.25,2.547) A9(2.6,2.548) A12(3.4,2.548) B1(3.1,2.548) B4(2.3,2.547) B5(1.75,2.548) B6(0.75,2.547) B7(-0.75,2.547) B8(-1.75,2.548) B9(-2.3,2.547) B12(-3.1,2.548)
  Keep-Out Layer circle w0.127: c2.89,1.103 r0.325
  Keep-Out Layer circle w0.127: c-2.89,1.103 r0.325
  silkscreen extent -4.33,-5.15 4.33,1.63
VLS252010 [mm] "VLS2016"
  rect 0.7x2 smd: 1(0.95,0) 2(-0.95,0)
  silkscreen extent -1,-1.1 1,1.1
WS2812LED-2020 [mm]
  rect 0.6x0.7 smd: 1(-0.915,0.55) 2(-0.915,-0.55) 3(0.915,-0.55) 4(0.915,0.55)
  silkscreen extent -0.5,-1 0,1

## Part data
BT1: library part Battery, "Multicell Battery"
C1 C2 C3 C4 C5 C6 C7 C8 C9 C10 C11 C12 C13 C14 C15 C16 C17 C18 C19 C20 C21 C22 C23 C24 C25 C26 C27 C28 C29 C30 C31 C32 C33 C34 C35 C36 C37 C38 C39 C40 C41 C42 C43 C44 C45 C46 C47 C48 C49 C50 C51 C52 C53 C54: library part CAP, "普通小电容"
D1: library part Diode, "普通二极管"
D2 D3 D4 D5 D6 D7: "TVS放电管SMBJ5.0CA"
D8: "普通二极管"
J5: library part MCX_IPEX
L1: library part L, "普通电感"
L2: library part L0402
P1: library part "USB A Right Angle Stacked", "CONN RECEPT STACKED USB A RT ANG"
P2: "Header, 20-Pin"
P3 P4: "Header, 3-Pin"
P5 P10: library part "Header 15", "Header, 15-Pin"
P7: library part FPC6_CTP_H1
P8: library part FPC6_CTP_H1, "FPC6，C2919536_0.5MMP数_6翻盖式下接配0.2排线蓝色卡扣"
P9: "Header, 24-Pin"
P11: "Header, 30-Pin"
P12: library part FPC26, "FPC, 26-Pin, 1H"
P13: "Header, 14-Pin, Dual row"
R1 R2 R3 R4 R5 R6 R7 R8 R9 R10 R11 R12 R13 R14 R15 R16 R17 R18 R19 R20 R21 R22 R23 R24 R25 R26 R27 R28 R29 R30 R31 R32 R33 R34 R36 R37 R38 R39 R40 R41 R44 R45 R46 R47 R48 R49 R50 R51 R52 R53 R54 R55 R56: library part RES, "普通电阻"
TP1 TP2 TP3 TP4 TP5 TP6: library part TP, "Description"
U1: "800mA and 1A Low Dropout Positive Regulator 2.85V, 3.3V, 5V, and Adjustable", PackageDocument=revC
U2: library part PT4101
U3: library part AP6212
U7: library part LED-RGB_ws2812_2020

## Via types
v1: diameter 14, hole 8, Top Layer to Bottom Layer, tented both sides, 698 vias

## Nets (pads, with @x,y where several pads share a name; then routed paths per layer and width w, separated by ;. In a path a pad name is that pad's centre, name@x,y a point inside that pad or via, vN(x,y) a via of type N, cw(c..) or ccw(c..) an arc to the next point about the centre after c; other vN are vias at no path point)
AFVCC_CSI: C45.1 C49.2 M1.98 P11.2 | length 1766.4
  Top Layer w14: P11.2@626.45,1487.68 v1(626.45,1461.25) 649.7,1438 C45.1@656.7,1438 ; v1(1161.42,2633.72) M1.98@1161.42,2677.17 ; M1.98@1161.42,2675.39 1161.42,2736.72 C49.2@1161.7,2737
  Layer 1 w14: v1(626.45,1461.25) 626.45,2398.75 891.7,2664 1131.13,2664 v1(1161.42,2633.72)
AGND: C38.2 C39.1 C44.1 C46.1 C51.1 M1.8 R27.1 R31.2 R33.1 R34.2 R55.2 R56.2 TP6.1 U6.2 | length 4510.6
  Top Layer w6: v1(1161.42,1370.72) 1161.42,1335.28 R27.1@1192.7,1304
  Top Layer w8: M1.8@1161.42,1417.32 M1.8@1161.7,1417.04
  Top Layer w10: R33.1@851.7,1181 942.7,1181 TP6.1@946.7,1185 ; R34.2@985.7,1311 v1(985.7,1331.5) R31.2@985.7,1352 ; v1(1035.7,1103) C46.1@1076.7,1103 C51.1@1113.7,1103 ; v1(2047.7,674) C39.1@2068.7,674 R55.2@2102.7,674 ; v1(4034.7,674) C44.1@4055.7,674 R56.2@4088.7,674
  Top Layer w12: R33.1@851.7,1181 851.7,1246.6 v1(852.1,1247) 852.1,1275.4 863.7,1287 922.7,1287 C38.2@940.7,1269 ; v1(1161.42,1370.72) M1.8@1161.42,1417.32
  Layer 1 w20: v1(985.7,1331.5) 1122.2,1331.5 v1(1161.42,1370.72)
  Bottom Layer w10: v1(985.7,1331.5) 1035.7,1281.5 v1(1035.7,1103) 1035.7,971 1332.7,674 v1(2047.7,674) v1(4034.7,674)
  Bottom Layer w20: v1(852.1,1247) 901.2,1247 v1(985.7,1331.5)
AP-SDC1-CLK: C6.2 R44.1 U3.17 | length 1764.5
  Top Layer w5: C6.2@1333.57,2882.37 U3.17@1333.56,2938.43
  Top Layer w6: v1(2162.7,1916) R44.1@2182.7,1916
  Layer 1 w5: v1(1333.7,2902) 1366.7,2869 1366.7,2200 1457.7,2109 1617.7,2109 1644.7,2082 2097.7,2082 2128.7,2051 2128.7,1950 v1(2162.7,1916)
AP-SDC1-CMD: M1.49 R22.2 U3.16 | length 1803.1
  Top Layer w4.72: U3.16@1298.13,2938.43 1298.13,2904 1298.13,2882.44 R22.2@1298.19,2882.37 ; v1(2085.09,1913.38) M1.49@2125.98,1913.38
  Layer 1 w4.72: v1(1297.7,2904) 1349.7,2852 1349.7,2186 1441.7,2094 1612.7,2094 1640.7,2066 2096.7,2066 2111.7,2051 2111.7,1940 v1(2085.09,1913.38)
AP-SDC1-D0: M1.50 R23.2 U3.18 | length 1734.6
  Top Layer w5: R23.2@1368.94,2882.37 1368.99,2882.42 U3.18@1368.99,2938.43 ; M1.50@2125.98,1946.85 v1(2164.55,1946.85)
  Layer 1 w4: v1(1368.7,2901) 1388.7,2881 1388.7,2203 1469.7,2122 1626.7,2122 1652.7,2096 2103.7,2096 2141.7,2058 2141.7,1969.7 v1(2164.55,1946.85)
AP-SDC1-D1: M1.51 R24.2 U3.19 | length 1693
  Top Layer w4: M1.51@2125.98,1980.31 v1(2170.39,1980.31)
  Top Layer w4.72: R24.2@1404.32,2882.37 1404.43,2882.48 U3.19@1404.42,2938.43
  Layer 1 w4: v1(1404.7,2903) 1404.7,2212 1481.7,2135 1634.7,2135 1660.7,2109 2109.7,2109 2154.7,2064 2154.7,1996 v1(2170.39,1980.31)
AP-SDC1-D2: M1.52 R20.2 U3.14 | length 1708.5
  Top Layer w5: v1(2050.7,2013) 2125.21,2013 M1.52@2125.98,2013.78
  Top Layer w5.91: U3.14@1227.26,2938.43 1227.26,2882.55 R20.2@1227.44,2882.37
  Layer 1 w4: v1(1226.7,2904) 1244.7,2886 1318.7,2812 1318.7,2157 1410.7,2065
  Layer 1 w5: 1410.7,2065 1601,2065 1653,2013 v1(2050.7,2013)
AP-SDC1-D3: M1.53 R21.2 U3.15 | length 1661.7
  Top Layer w5: v1(2050.7,2047) 2125.74,2047 M1.53@2125.98,2047.24
  Top Layer w5.91: U3.15@1262.69,2938.43 1262.69,2882.5 R21.2@1262.82,2882.37
  Layer 1 w4: v1(1263.7,2905) 1263.7,2894 1334.7,2823 1334.7,2318
  Layer 1 w5: 1334.7,2318 1334.7,2172 1427.7,2079 1608,2079 1640,2047 v1(2050.7,2047)
AP-UART1-CTS: M1.57 R4.2 U3.41 | length 2261.1
  Top Layer w5: v1(1262.69,3335.01) U3.41@1262.69,3379.37 R4.2@1262.69,3433.37 ; M1.57@2125.98,2181.1 v1(2167.6,2181.1)
  Bottom Layer w4: v1(1262.69,3335.01) 1262.69,3250.99 1185.7,3174 1185.7,2869 1212.7,2842 1212.7,2348.3 1461,2100 1951.7,2100 1970.7,2119 2105.5,2119 v1(2167.6,2181.1)
AP-UART1-RTS: M1.56 U3.44 | length 2254
  Top Layer w5: M1.56@2125.98,2147.64 v1(2166.06,2147.64)
  Bottom Layer w4: v1(1156.39,3379.37) 1244.7,3291.06 1244.7,3259 1171,3185.3 1171,2875 1176.7,2869.3 1176.7,2364.3 1454,2087 1958.7,2087 1974.7,2103 2121.43,2103 v1(2166.06,2147.64)
AP-UART1-RX: M1.55 U3.42 | length 2257.1
  Top Layer w5: v1(1226.7,3275) 1226.7,3378.81 U3.42@1227.26,3379.37 ; M1.55@2125.98,2114.17 v1(2167.87,2114.17)
  Bottom Layer w4: v1(1226.7,3275) 1131.7,3180 1131.7,2384.3 1441,2075 1968.7,2075 1986.7,2093 2146.7,2093 v1(2167.87,2114.17)
AP-UART1-TX: M1.54 U3.43 | length 2267.3
  Top Layer w5: v1(1191.83,3273.87) U3.43@1191.83,3379.37 ; M1.54@2125.98,2080.71 v1(2168.99,2080.71)
  Bottom Layer w5: v1(1191.83,3273.87) 1115.7,3197.75 1115.7,2380.3 1435,2061 1973.7,2061 1993.41,2080.71 v1(2168.99,2080.71)
AP-WAKE-BT: M1.60 R14.1 U3.6 | length 2099.9
  Top Layer w5.91: R14.1@1057.69,3167 1079.7,3167 1087.8,3158.9 U3.6@1113.09,3158.9 1210.8,3158.9 v1(1232.7,3137) ; v1(2076.19,2281.49) M1.60@2125.98,2281.49
  Bottom Layer w4: v1(1232.7,3137) 1200.7,3105 1200.7,2974 1242.7,2932 1242.7,2343.3 1470,2116 1954.97,2116 2001.72,2162.75 2029.45,2162.75 2076.19,2209.49 v1(2076.19,2281.49)
AP_RST: M1.103 S4.2 | length 1098.3
  Top Layer w6: S4.2@247.58,3314.08 v1(302.15,3314.08) ; M1.103@994.09,2677.17 v1(994.09,2827.39)
  Layer 1 w6: v1(302.15,3314.08) 507.41,3314.08 939.49,2882 v1(994.09,2827.39)
AVDD_CSI: C29.1 C37.1 C48.2 M1.97 P11.7 P12.3 | length 2292
  Top Layer w10: v1(527.7,1438) 528.02,1438.32 P11.7@528.02,1487.68 ; v1(565.7,1234) 565.9,1233.8 P12.3@565.9,1195.68 565.9,1180.8 C29.1@584.7,1162
  Top Layer w16: C48.2@1194.7,2737 1194.88,2736.82 M1.97@1194.88,2675.39
  Layer 1 w20: v1(527.7,1438) 536.7,1447 536.7,1588 499.7,1625 499.7,2486 756.7,2743 1165.7,2743 v1(1194.7,2714)
  Bottom Layer w10: v1(527.7,1438) 528.02,1438 565.93,1400.09 565.93,1234.23 v1(565.7,1234)
BT-RST-N: M1.62 R5.2 U3.34 | length 1591.2
  Top Layer w4.72: U3.34@1510.72,3379.37 1510.72,3140.98 1523.7,3128 1523.7,2977 1565.7,2935 1565.7,2864 R5.2@1547.7,2846 v1(1521.7,2820) ; M1.62@2125.98,2348.42 2126.56,2349 v1(2162.7,2349)
  Bottom Layer w4.72: v1(1521.7,2820) 1562.7,2779 1562.7,2646 1625.7,2583 1996.7,2583 2123.7,2456 2123.7,2388 v1(2162.7,2349)
BT-WAKE-AP: M1.63 U3.7 | length 1556.3
  Top Layer w5.91: U3.7@1113.09,3123.47 1201.24,3123.47 v1(1234.7,3090) ; v1(2069.59,2381.89) M1.63@2125.98,2381.89
  Bottom Layer w4: v1(1234.7,3090) 1234.7,3058.3 1261.7,3031.3 1261.7,3002 1315.7,2948 1315.7,2679 1439.7,2555 1969.7,2555 2069.59,2455.11 v1(2069.59,2381.89)
CC1: D2.2 J1.A5 M1.116 | length 2048.7
  Top Layer w6: J1.A5@559.91,3664.7 559.91,3704.21 613.7,3758 691.7,3758 728.7,3721 728.7,3578 577.7,3427 577.7,3149 684.7,3042 684.7,2327 730.21,2281.49 M1.116@866.14,2281.49
  Top Layer w8: D2.2@538.24,3572 538.24,3590.54 559.91,3612.21 J1.A5@559.91,3664.7
CC2: D5.2 J1.B5 M1.115 | length 2178.9
  Top Layer w6: J1.B5@441.8,3664.7 441.8,3699.1 513.7,3771 695.7,3771 748.7,3718 748.7,3580 588.7,3420 588.7,3161 699.06,3050.64 699.06,2343.64 727.74,2314.96 M1.115@866.14,2314.96
  Top Layer w8: J1.B5@441.8,3664.7 441.8,3625.9 448.7,3619 467.7,3619 482.16,3604.54 D5.2@482.16,3572
CK_N: M1.84 P2.8 P6.16 P10.5 R39.1 | length 2348.8
  Top Layer w6: M1.84@1629.92,2677.17 1619.7,2687.38 1619.7,2720 cw(c1631.7,2720) 1631.7,2732 1797,2732 1860.7,2795.7 1860.7,3072 2070.7,3282 v1(2222.7,3282) R39.1@2251.7,3282 ; P2.8@1954.19,3703.31 1954.19,3735.49 v1(1959.7,3741) ; P10.5@2022.59,3450.17 v1(2022.59,3573)
  Layer 1 w5: v1(1959.7,3741) 1959.7,3708 1925.7,3674 1925.7,3614 1967.72,3571.98 1967.72,3566.58 1974.7,3559.6 1974.7,3557 1989.7,3557 2005.7,3573 v1(2022.59,3573)
  Layer 1 w6: v1(2022.59,3573) 2022.59,3331.11 2060.7,3293 2211.7,3293 v1(2222.7,3282)
  Bottom Layer w6: P6.16@1816.4,3703.31 1816.4,3693.3 1822.18,3687.52 1822.18,3687.2 1826.86,3682.52 1827.18,3682.52 1838.7,3671 1838.7,3570 1859.02,3549.68 1953.44,3549.68 1963.7,3559.94 1963.7,3585 1970.7,3592 2003.59,3592 v1(2022.59,3573)
CK_P: M1.85 P2.7 P6.15 P10.6 R38.1 | length 2336.9
  Top Layer w6: M1.85@1596.45,2677.17 1606.7,2687.41 1606.7,2728 cw(c1627.7,2728) 1627.7,2749 1796,2749 1847.7,2800.7 1847.7,3077 2086.7,3316 v1(2221.7,3316) R38.1@2251.7,3316 ; P2.7@1973.88,3703.31 1973.88,3731.18 v1(1983.7,3741) ; P10.6@1983.22,3450.17 v1(1983.22,3573)
  Layer 1 w5: v1(1983.22,3573) 1936.2,3620.02 1936.2,3668.5 1983.7,3716 v1(1983.7,3741)
  Layer 1 w6: v1(1983.22,3573) 2002.22,3592 2033.62,3592 2041.7,3583.92 2041.7,3337 2072.7,3306 2211.7,3306 v1(2221.7,3316)
  Bottom Layer w6: P6.15@1796.71,3703.31 1796.71,3691.99 1825.7,3663 1825.7,3563 1851.7,3537 1959.7,3537 1983.22,3560.52 v1(1983.22,3573)
CLK-FANOUT1: M1.64 R17.1 | length 1099.8
  Top Layer w5: v1(1612.54,2948.84) 1639.7,2976 R17.1@1639.7,2981 ; M1.64@2125.98,2415.35 v1(2168.05,2415.35)
  Bottom Layer w5: v1(1612.54,2948.84) 1575.7,2912 1575.7,2654 1631.7,2598 2007.7,2598 2168.05,2437.65 v1(2168.05,2415.35)
CPU-RX: M1.46 P4.1 | length 1486
  Top Layer w5: M1.46@2125.98,1812.99 2087.71,1812.99 2014.7,1886 2014.7,2585.85 2134.7,2705.85 2134.7,2853 2090.7,2897 2090.7,2930 2090.7,3089 P4.1@2142.7,3141
CPU-TX: M1.47 P4.2 | length 1342.9
  Top Layer w5: P4.2@2142.7,3041 2190.03,2993.67
  Top Layer w6: M1.47@2125.98,1846.46 2086.24,1846.46 2030.7,1902 2030.7,2587 2190.03,2746.33 2190.03,2912.33 2190.03,2993.67
CTP_INT: M1.38 P2.17 P7.4 P8.5 R11.2 | length 7149
  Top Layer w4.72: R11.2@1668.2,3382 1668.2,3392.5 1687.7,3412 1687.7,3746 1729.7,3788 v1(1742.7,3788) 1777.03,3753.67 P2.17@1777.03,3703.31 ; 3487.18,90 3495.07,82.11 P8.5@3495.07,25.31
  Top Layer w6: M1.38@2125.98,1545.28 v1(2169.98,1545.28) ; v1(2712.7,3589) 2767.7,3589 3487.18,2869.52 3487.18,1649.48 v1(3486.7,1649) 3487.18,1648.52 3487.18,90
  Bottom Layer w4.72: v1(1742.7,3788) 1839.7,3885 2657.7,3885 2700.86,3841.84 P7.4@2700.86,3703.68
  Bottom Layer w6: v1(2169.98,1545.28) 3194.98,1545.28 3298.7,1649 v1(3486.7,1649) ; P7.4@2700.86,3703.68 2700.86,3683.16 2691.7,3674 2691.7,3610 v1(2712.7,3589)
CTP_RST: M1.37 P2.18 P7.1 P8.2 R12.2 | length 7251.2
  Top Layer w4.72: R12.2@1707.7,3382 1727.7,3402 1727.7,3635 1700.7,3662 1700.7,3738 1724.7,3762 v1(1725.7,3762) 1736,3762 1759.94,3738.06 1759.94,3724.69 1757.34,3722.09 P2.18@1757.34,3703.31 ; v1(2807.7,3704) 2807.7,3634 2833.02,3608.68 3546.24,2895.47 v1(3546.24,1629.92) 3546.24,135.47 3554.13,127.58 P8.2@3554.13,25.31
  Top Layer w6: M1.37@2125.98,1511.81 2165.51,1511.81 v1(2175.7,1522)
  Bottom Layer w4.72: v1(1725.7,3762) 1725.7,3797 1824.34,3895.64 2681.06,3895.64 2759.91,3816.79 P7.1@2759.91,3703.68 ; v1(2175.7,1522) 3208.7,1522 3316.62,1629.92 v1(3546.24,1629.92)
  Bottom Layer w6: P7.1@2759.91,3703.68 2807.38,3703.68 v1(2807.7,3704)
CTP_SCL: M1.23 P2.19 P7.6 P8.4 P10.11 R13.2 | length 7472.9
  Top Layer w6: v1(1744.7,3731) 1737.66,3723.96 P2.19@1737.66,3703.31 1737.66,3673.04 1786.37,3624.33 P10.11@1786.37,3573 1786.7,3572.67 R13.2@1786.7,3382 ; v1(2661.49,3740.21) 2661.49,3640.21 2689.7,3612 2768.7,3612 3506.87,2873.84 3506.87,94 3514.76,86.11 P8.4@3514.76,25.31
  Bottom Layer w4.72: v1(1744.7,3731) 1871.7,3858 2635.7,3858 2661.49,3832.21 v1(2661.49,3740.21)
  Bottom Layer w6: v1(1663.38,1417.32) 1663.38,1432.68 1708.7,1478 v1(3506.7,1478) ; P7.6@2661.49,3703.68 v1(2661.49,3740.21)
CTP_SDA: M1.24 P2.20 P7.5 P8.3 P10.12 R25.2 | length 7494.7
  Top Layer w5.12: 3526.55,108 3534.44,100.11 P8.3@3534.44,25.31
  Top Layer w6: v1(1724.7,3740) 1717.97,3733.27 P2.20@1717.97,3703.31 1717.97,3667.73 1747,3638.7 P10.12@1747,3573 1747,3382.2 R25.2@1747.2,3382 ; v1(2681.17,3732.53) 2681.17,3647.53 2701.7,3627 2781.7,3627 3526.55,2882.15 3526.55,108
  Bottom Layer w5.12: v1(1724.7,3740) 1731.27,3746.57 1732.09,3746.57 1741.13,3755.61 1741.13,3756.43 1854.7,3870 2647.7,3870 2681.17,3836.53 v1(2681.17,3732.53)
  Bottom Layer w6: v1(1696.85,1417.32) 1696.85,1435.15 1718.7,1457 v1(3526.7,1457) ; P7.5@2681.17,3703.68 v1(2681.17,3732.53)
D0_N: M1.91 P2.3 P6.24 P10.8 R41.1 | length 2141.1
  Top Layer w6: M1.91@1395.67,2677.17 1385.2,2687.63 1385.2,2707.5 1432.7,2755 1522.7,2755 1574.7,2807 1698.7,2807 1723.7,2832 1723.7,3155 1891.7,3323 1891.7,3437.39 P10.8@1904.48,3450.17 v1(1904.48,3573) ; v1@1973.7,3657 2027.7,3657 2052.62,3681.92 P2.3@2052.62,3703.31 ; v1(2222.7,3210) R41.1@2251.7,3210
  Layer 1 w6: v1(1904.48,3573) 1903.7,3572.22 1903.7,3347.54 2028.24,3223 2209.7,3223 v1(2222.7,3210)
  Bottom Layer w6: v1(1904.48,3573) 1973.88,3642.4 P6.24@1973.88,3703.31
  other v1: 1973.88,3657
D0_P: M1.92 P2.2 P6.23 P10.9 R40.1 | length 2259.4
  Top Layer w6: M1.92@1362.2,2677.17 1373.7,2688.66 1373.7,2715 1425.7,2767 1515.7,2767 1568.7,2820 1692.7,2820 1709.7,2837 1709.7,3160 1876.7,3327 1876.7,3438.57 P10.9@1865.11,3450.17 v1(1865.11,3573) ; v1(1953.7,3651) 1962.7,3642 2029.7,3642 2072.3,3684.6 P2.2@2072.3,3703.31 ; v1(2222.7,3246) R40.1@2251.7,3246
  Layer 1 w6: v1(1865.11,3573) 1884.11,3592 1911.7,3592 1922.7,3581 1922.7,3344.8 2032.5,3235 2211.7,3235 v1(2222.7,3246)
  Bottom Layer w6: v1(1865.11,3573) 1880.7,3573 1954.19,3646.49 P6.23@1954.19,3703.31
D1_N: M1.89 P2.5 P6.26 P10.2 R37.1 | length 2040.8
  Top Layer w6: M1.89@1462.6,2677.17 1452.2,2687.56 1452.2,2713.5 1458.7,2720 1556.7,2720 1609.7,2773 1722,2773 ccw(c1722,2837) 1786,2837 1786,3130.3 2006.7,3351 v1(2221.7,3351) R37.1@2251.7,3351 ; v1(2013.25,3674) P2.5@2013.25,3703.31 ; v1(2099.7,3625) 2129.7,3625 2140.7,3614 P10.2@2140.7,3573 P10.2@2140.7,3450.17
  Layer 1 w6: v1(2013.25,3674) 2062.25,3625 v1(2099.7,3625) 2099.7,3600 2083.7,3584 2083.7,3417 2137.7,3363 2209.7,3363 v1(2221.7,3351)
  Bottom Layer w6: v1(2013.25,3674) P6.26@2013.25,3703.31
D1_P: M1.90 P2.4 P6.25 P10.3 R7.1 | length 2039.4
  Top Layer w6: M1.90@1429.13,2677.17 1440.7,2688.73 1440.7,2718 cw(c1454.7,2718) 1454.7,2732 1549.7,2732 1603.7,2786 1719,2786 ccw(c1719,2840) 1773,2840 1773,3138.3 2020.7,3386 v1(2221.7,3386) R7.1@2251.7,3386 ; v1(2012.7,3733) 2022.7,3733 2032.93,3722.77 P2.4@2032.93,3703.31 ; P10.3@2101.33,3450.17 v1(2101.33,3573)
  Layer 1 w6: v1(2012.7,3733) 2021.7,3733 2117.7,3637 2117.7,3589.37 v1(2101.33,3573) 2101.33,3418.37 2143.7,3376 2211.7,3376 v1(2221.7,3386)
  Bottom Layer w6: P6.25@1993.56,3703.31 1993.56,3720.8 2005.76,3733 v1(2012.7,3733)
D2_N: M1.87 P2.11 P6.28 | length 1540.3
  Top Layer w5: P2.11@1895.14,3703.31 1900.2,3708.37 1900.2,3741.35 1900.7,3741.85 1900.7,3742 1930.7,3772 2032.7,3772 2052.7,3752 v1(2052.7,3744)
  Top Layer w6: v1(1807.7,3656.11) 1813.59,3662 1870.73,3662 1895.14,3686.41 P2.11@1895.14,3703.31
  Layer 1 w6: v1(1529.53,2677.17) 1519.7,2686.99 1519.7,2756 1565.7,2802 1605,2802 1653.7,2850.7 1653.7,3266 1610.7,3309 1610.7,3451 1704.12,3544.42 1807.7,3648 v1(1807.7,3656.11)
  Bottom Layer w5: P6.28@2052.62,3703.31 2052.62,3743.92 v1(2052.7,3744)
D2_P: M1.88 P2.10 P6.27 | length 1541
  Top Layer w5: P2.10@1914.82,3703.31 1910.7,3707.43 1910.7,3737 1933.7,3760 2023.7,3760 v1(2032.93,3750.77)
  Top Layer w6: v1(1782.7,3652) 1795.59,3639.11 1814.74,3639.11 1825.63,3650 1875.7,3650 1914.82,3689.12 P2.10@1914.82,3703.31
  Layer 1 w6: v1(1496.06,2677.17) 1506.7,2687.8 1506.7,2760 1563.7,2817 1601,2817 1640.7,2856.7 1640.7,3260 1598.7,3302 1598.7,3458 1782.7,3642 v1(1782.7,3652)
  Bottom Layer w4: P6.27@2032.93,3703.31 v1(2032.93,3750.77)
D3_N: M1.81 P2.13 P6.18 | length 1264.3
  Top Layer w7.87: P2.13@1855.77,3703.31 v1(1855.77,3763)
  Layer 1 w6: v1(1730.31,2677.17) 1730.31,2694.39 1721.7,2703 1721.7,3514 1847.7,3640 1847.7,3723 1855.77,3731.07 v1(1855.77,3763)
  Bottom Layer w7.87: P6.18@1855.77,3703.31 v1(1855.77,3763)
D3_P: M1.82 P2.12 P6.17 | length 1314.3
  Top Layer w7.87: v1(1836.08,3740.38) 1836.08,3779.38 1842.7,3786 1862.7,3786 1875.45,3773.25 P2.12@1875.45,3703.31
  Layer 1 w6: v1(1696.85,2677.17) 1696.85,2695.15 1705.7,2704 1705.7,3514.26 1836.08,3644.65 v1(1836.08,3740.38)
  Bottom Layer w7.87: P6.17@1836.08,3703.31 v1(1836.08,3740.38)
DSI-RESET: M1.94 P2.15 P9.7 | length 6130.1
  Top Layer w4: M1.94@1295.27,2677.17 1295.27,2715.57 1391.7,2812 v1(1439.7,2812)
  Top Layer w6: v1(1385.7,3596) 1486.7,3596 1619.55,3728.85 1619.55,3798.85 1671.42,3850.72 1816.4,3850.72 ; P2.15@1816.4,3703.31 1816.4,3850.72 ; P9.7@2888.5,135.63 2888.5,156.12 2880.61,164 2880.61,3150.09 2179.98,3850.72 1816.4,3850.72
  Layer 1 w4: v1(1385.7,3596) 1385.7,3227 1444.7,3168 1444.7,2817 v1(1439.7,2812)
DVDD_CSI: C25.2 C28.1 C30.1 M1.95 P11.3 R3.1 | length 2360.5
  Top Layer w6: R3.1@545.7,1126 563.7,1144 606.7,1144 C30.1@624.7,1162
  Top Layer w10: v1(606.76,1464.06) P11.3@606.76,1487.68
  Top Layer w14: v1(606.76,1464.06) 606.76,1438.82 C28.1@607.58,1438 631.14,1414.44 631.14,1366.44 611.7,1347 611.7,1260 635.7,1236 635.7,1173 C30.1@624.7,1162 ; C25.2@1261.7,2737 v1(1261.7,2714) 1261.7,2675.5 M1.95@1261.81,2675.39
  Layer 1 w14: v1(606.76,1464.06) 567.7,1503.12 567.7,2422 859.7,2714 1129.7,2714 1180.7,2663 1236.7,2663 1261.7,2688 v1(1261.7,2714)
  Bottom Layer w14: v1@606.7,1464 v1(606.76,1464.06)
FEL: M1.105 S5.2 | length 1255.5
  Top Layer w6: S5.2@247.58,3526.08 247.58,3464.12 v1(263.7,3448) ; M1.105@927.17,2677.17 v1(927.17,2820)
  Top Layer w8: M1.105@925.7,2676.85 M1.105@927.17,2675.39
  Layer 1 w6: v1(263.7,3448) 263.7,3309 291.7,3281 501.7,3281 927.17,2855.54 v1(927.17,2820)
